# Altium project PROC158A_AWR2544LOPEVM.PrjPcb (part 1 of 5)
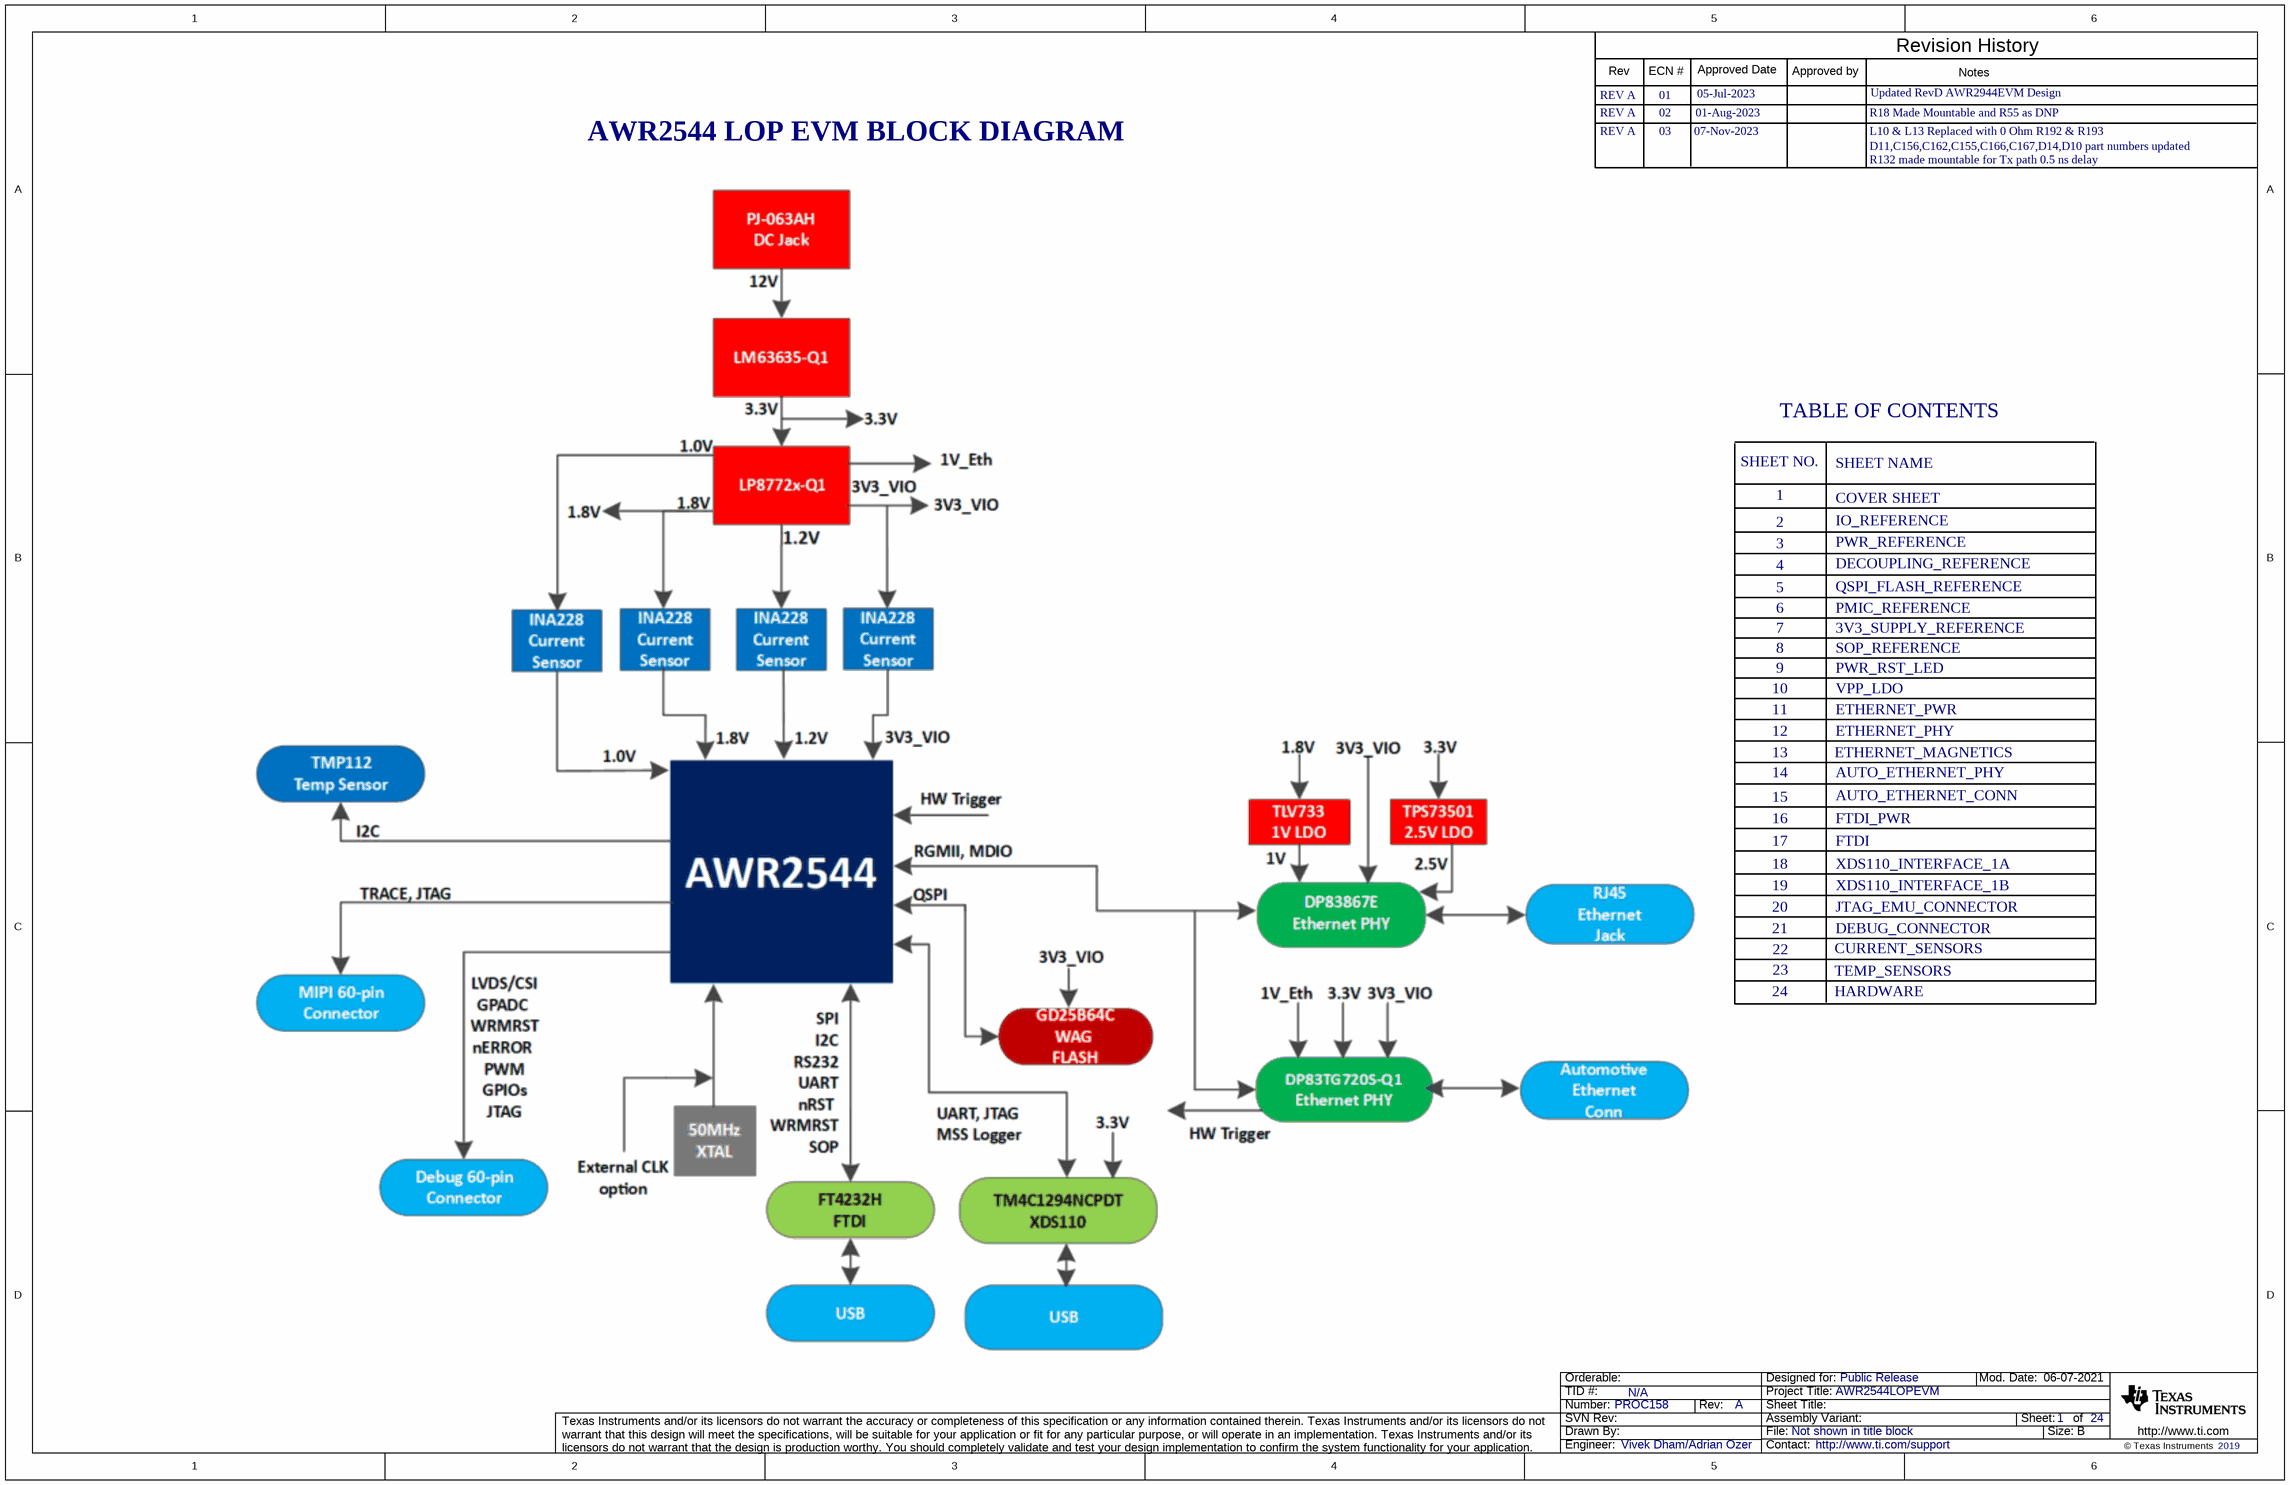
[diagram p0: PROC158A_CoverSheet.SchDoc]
CopyrightYear: 2019; PCB_Layout: Mistral; PCB_Rev: A; PRJ_Customer: Public Release; PRJ_Engineer: Vivek Dham/Adrian Ozer; PRJ_Number: PROC158; PRJ_Title: AWR2544LOPEVM; SCH_Rev: A; TechSupport: http://www.ti.com/support; TID: N/A
24 sheets, 718 parts. Net scope: global (net labels, ports and power ports of the same name join across sheets).
Board file: PROC158A_BRD.PcbDoc
Sheets:
  PROC158A_CoverSheet.SchDoc
  PROC158A_IO_Reference.SchDoc
  PROC158A_PWR_Reference.SchDoc
  PROC158A_Decoupling_Reference.SchDoc
  PROC158A_QSPI_Flash_Reference.SchDoc
  PROC158A_PMIC_Reference.SchDoc
  PROC158A_3V3_Supply_Reference.SchDoc
  PROC158A_SOP_Reference.SchDoc
  PROC158A_PWR_RST_LED.SchDoc
  PROC158A_VPP_LDO.SchDoc
  PROC158A_Ethernet_PWR.SchDoc
  PROC158A_Ethernet_PHY.SchDoc
  PROC158A_Ethernet_Magnetics.SchDoc
  PROC158A_Auto_Ethernet_PHY.SchDoc
  PROC158A_Auto_Ethernet_conn.SchDoc
  PROC158A_FTDI_PWR.SchDoc
  PROC158A_FTDI.SchDoc
  PROC158A_XDS110 Interface_1A.SchDoc
  PROC158A_XDS110 Interface_1B.SchDoc
  PROC158A_JTAG_EMU_Connector.SchDoc
  PROC158A_Debug_Connector.SchDoc
  PROC158A_Current_Sensors.SchDoc
  PROC158A_Temp_Sensor.SchDoc
  PROC158A_Hardware.SchDoc

## Sheet PROC158A_CoverSheet.SchDoc
size 431 x 279 mm; Date: Not shown in title block; ApprovedBy: Not shown in title block; CheckedBy: Not shown in title block; Author: Not shown in title block; CompanyName: Not shown in title block; Engineer: Not shown in title block; Organization: Not shown in title block; Address1: Not shown in title block; Address2: Not shown in title block; Address3: Not shown in title block; Address4: Not shown in title block; DocumentNumber: 1; Revision: Use project parameter SCH_Rev; SheetNumber: 1; SheetTotal: 24; PageSetup: Record=PageOptions¦CenterHorizontal=True¦CenterVertical=True¦PrintScale=1.00¦XCorrection=1.00¦YCorrection=1.00¦PrintKind=0¦BorderSize=5000000¦LeftOffset=0¦BottomOffset=0¦Orientation=2¦PaperLength=1000¦PaperWidth=1000¦Scale=100¦PaperSource=15¦PrintQuality=600¦MediaType=1¦DitherType=10¦PaperKind=Letter¦PrintScaleMode=1

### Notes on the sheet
- REV A
- Rev
- 01
- ECN #
- 05-Jul-2023
- Approved Date
- Approved by
- Updated RevD AWR2944EVM Design
- Revision History
- Notes
- AWR2544 LOP EVM BLOCK DIAGRAM
- 02
- 03
- 07-Nov-2023
- 01-Aug-2023
- R18 Made Mountable and R55 as DNP
- L10 & L13 Replaced with 0 Ohm R192 & R193
- D11,C156,C162,C155,C166,C167,D14,D10 part numbers updated
- R132 made mountable for Tx path 0.5 ns delay
- TABLE OF CONTENTS
- SHEET NO.
- 1
- SHEET NAME
- 2
- 3
- 4
- COVER SHEET
- IO_REFERENCE
- PWR_REFERENCE
- DECOUPLING_REFERENCE
- 5
- 7
- 6
- PMIC_REFERENCE
- QSPI_FLASH_REFERENCE
- 3V3_SUPPLY_REFERENCE
- 10
- 8
- 9
- PWR_RST_LED
- SOP_REFERENCE
- VPP_LDO
- 11
- 12
- 13
- ETHERNET_MAGNETICS
- ETHERNET_PWR
- ETHERNET_PHY
- 15
- 16
- 14
- FTDI_PWR
- AUTO_ETHERNET_CONN
- AUTO_ETHERNET_PHY
- 17
- 18
- 19
- XDS110_INTERFACE_1B
- XDS110_INTERFACE_1A
- FTDI
- 20
- 21
- 22
- CURRENT_SENSORS
- JTAG_EMU_CONNECTOR
- DEBUG_CONNECTOR
- 24
- 23
- HARDWARE
- TEMP_SENSORS

## Sheet PROC158A_IO_Reference.SchDoc
size A2; Date: Not shown in title block; ApprovedBy: Not shown in title block; CheckedBy: Not shown in title block; Author: Not shown in title block; CompanyName: Not shown in title block; Engineer: Not shown in title block; Organization: Not shown in title block; Address1: Not shown in title block; Address2: Not shown in title block; Address3: Not shown in title block; Address4: Not shown in title block; DocumentNumber: 2; Revision: Use project parameter SCH_Rev; SheetNumber: 2; SheetTotal: 24; PageSetup: Record=PageOptions¦CenterHorizontal=True¦CenterVertical=True¦PrintScale=1.00¦XCorrection=1.00¦YCorrection=1.00¦PrintKind=0¦BorderSize=5000000¦LeftOffset=0¦BottomOffset=0¦Orientation=2¦PaperLength=1000¦PaperWidth=1000¦Scale=100¦PaperSource=15¦PrintQuality=600¦MediaType=1¦DitherType=10¦PaperKind=Letter¦PrintScaleMode=1
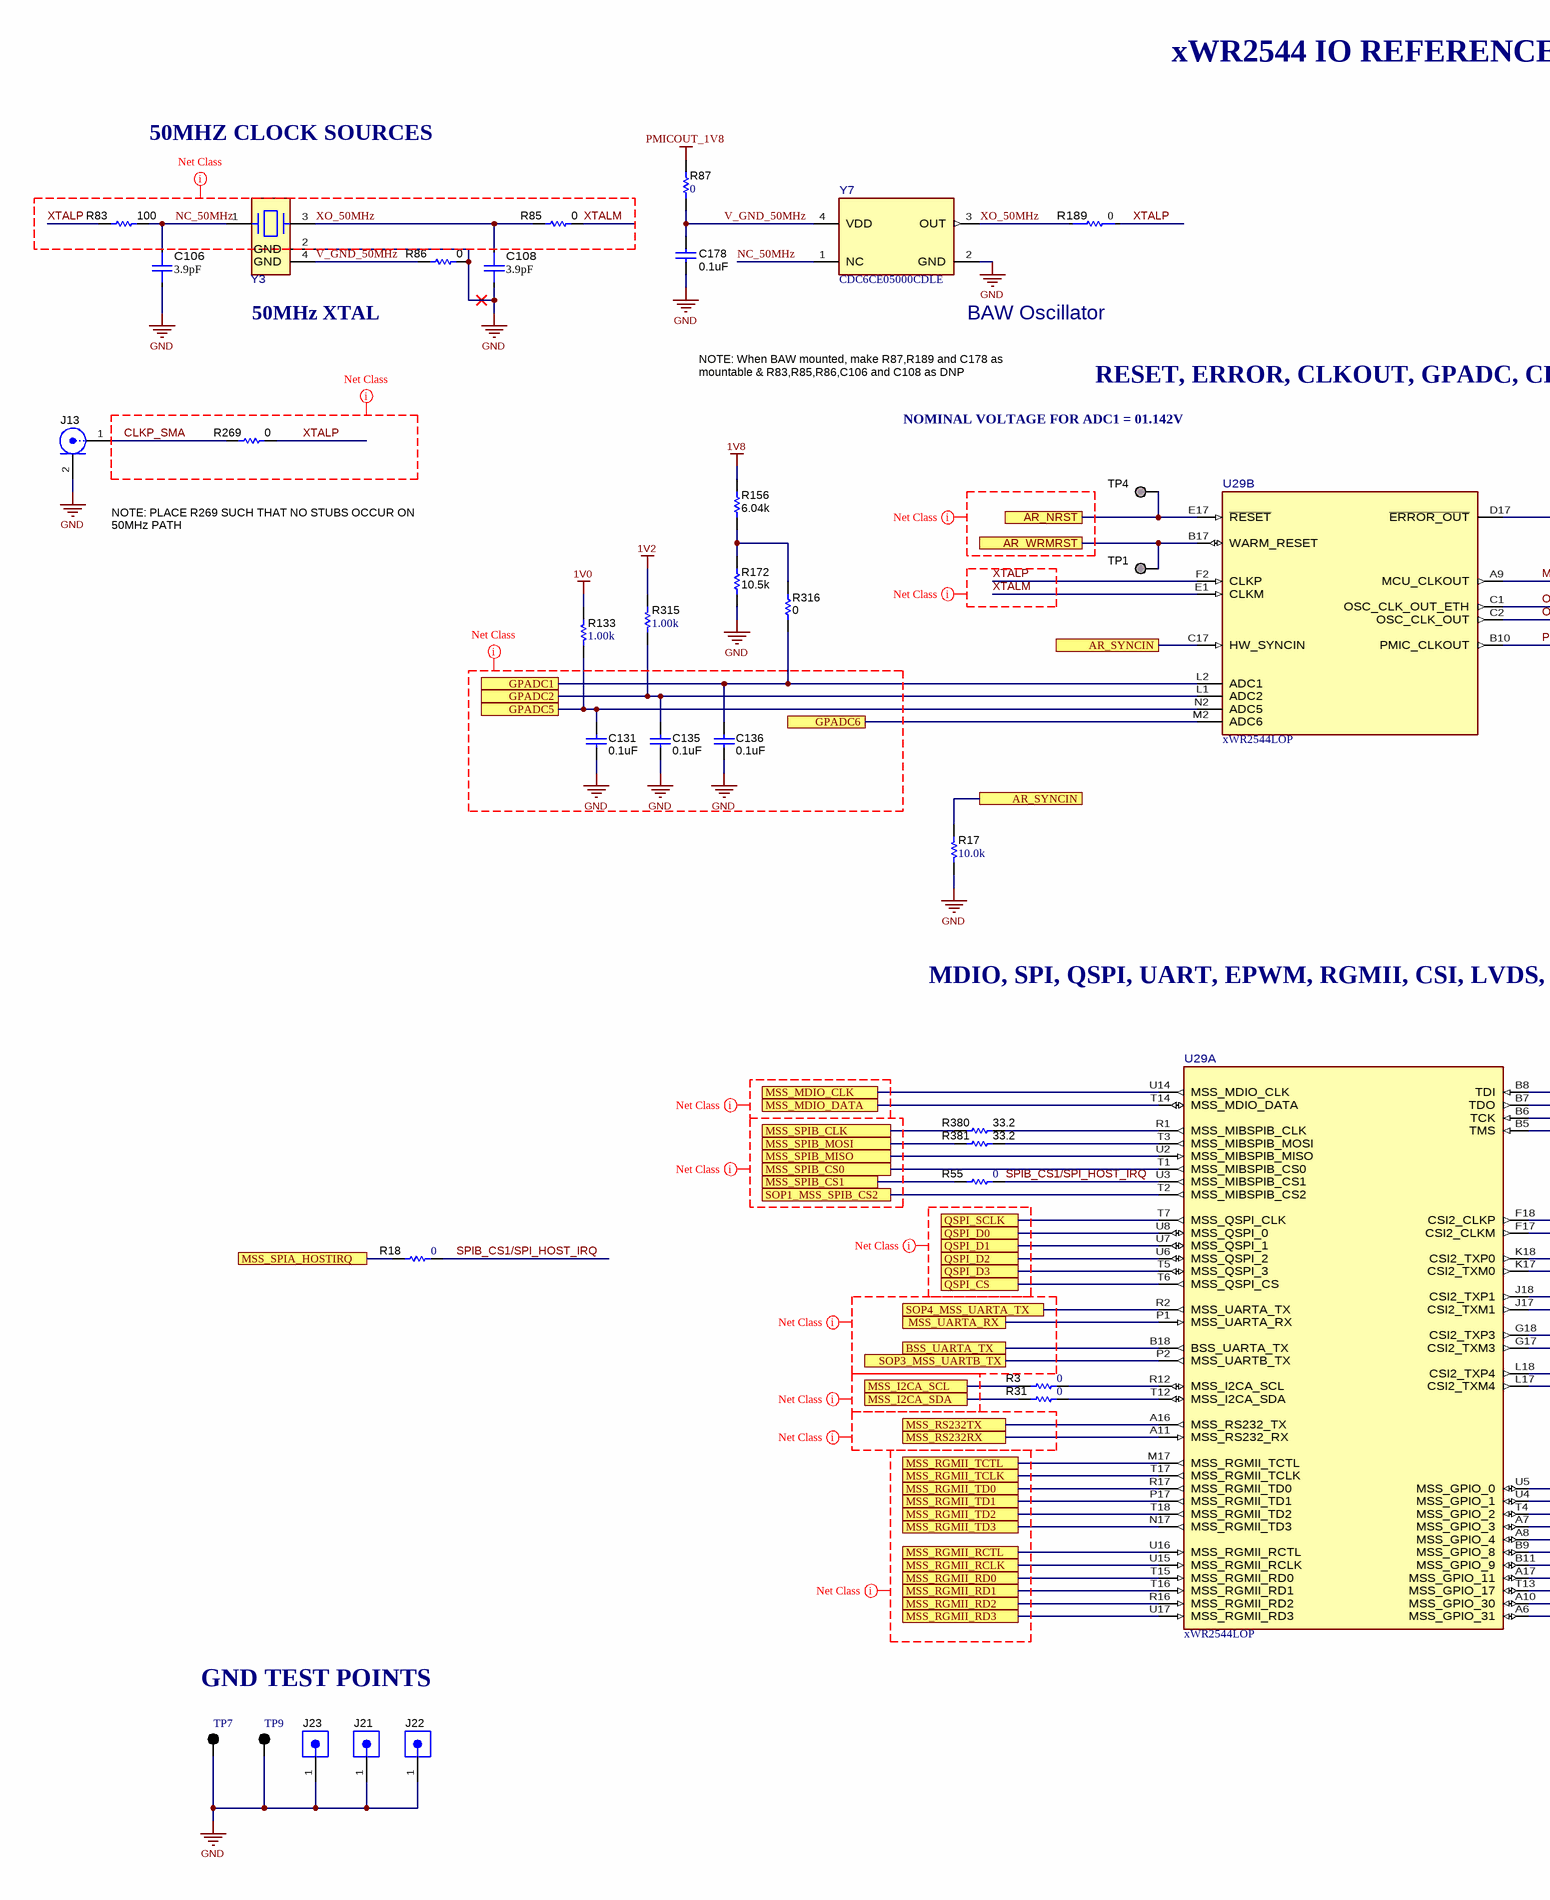
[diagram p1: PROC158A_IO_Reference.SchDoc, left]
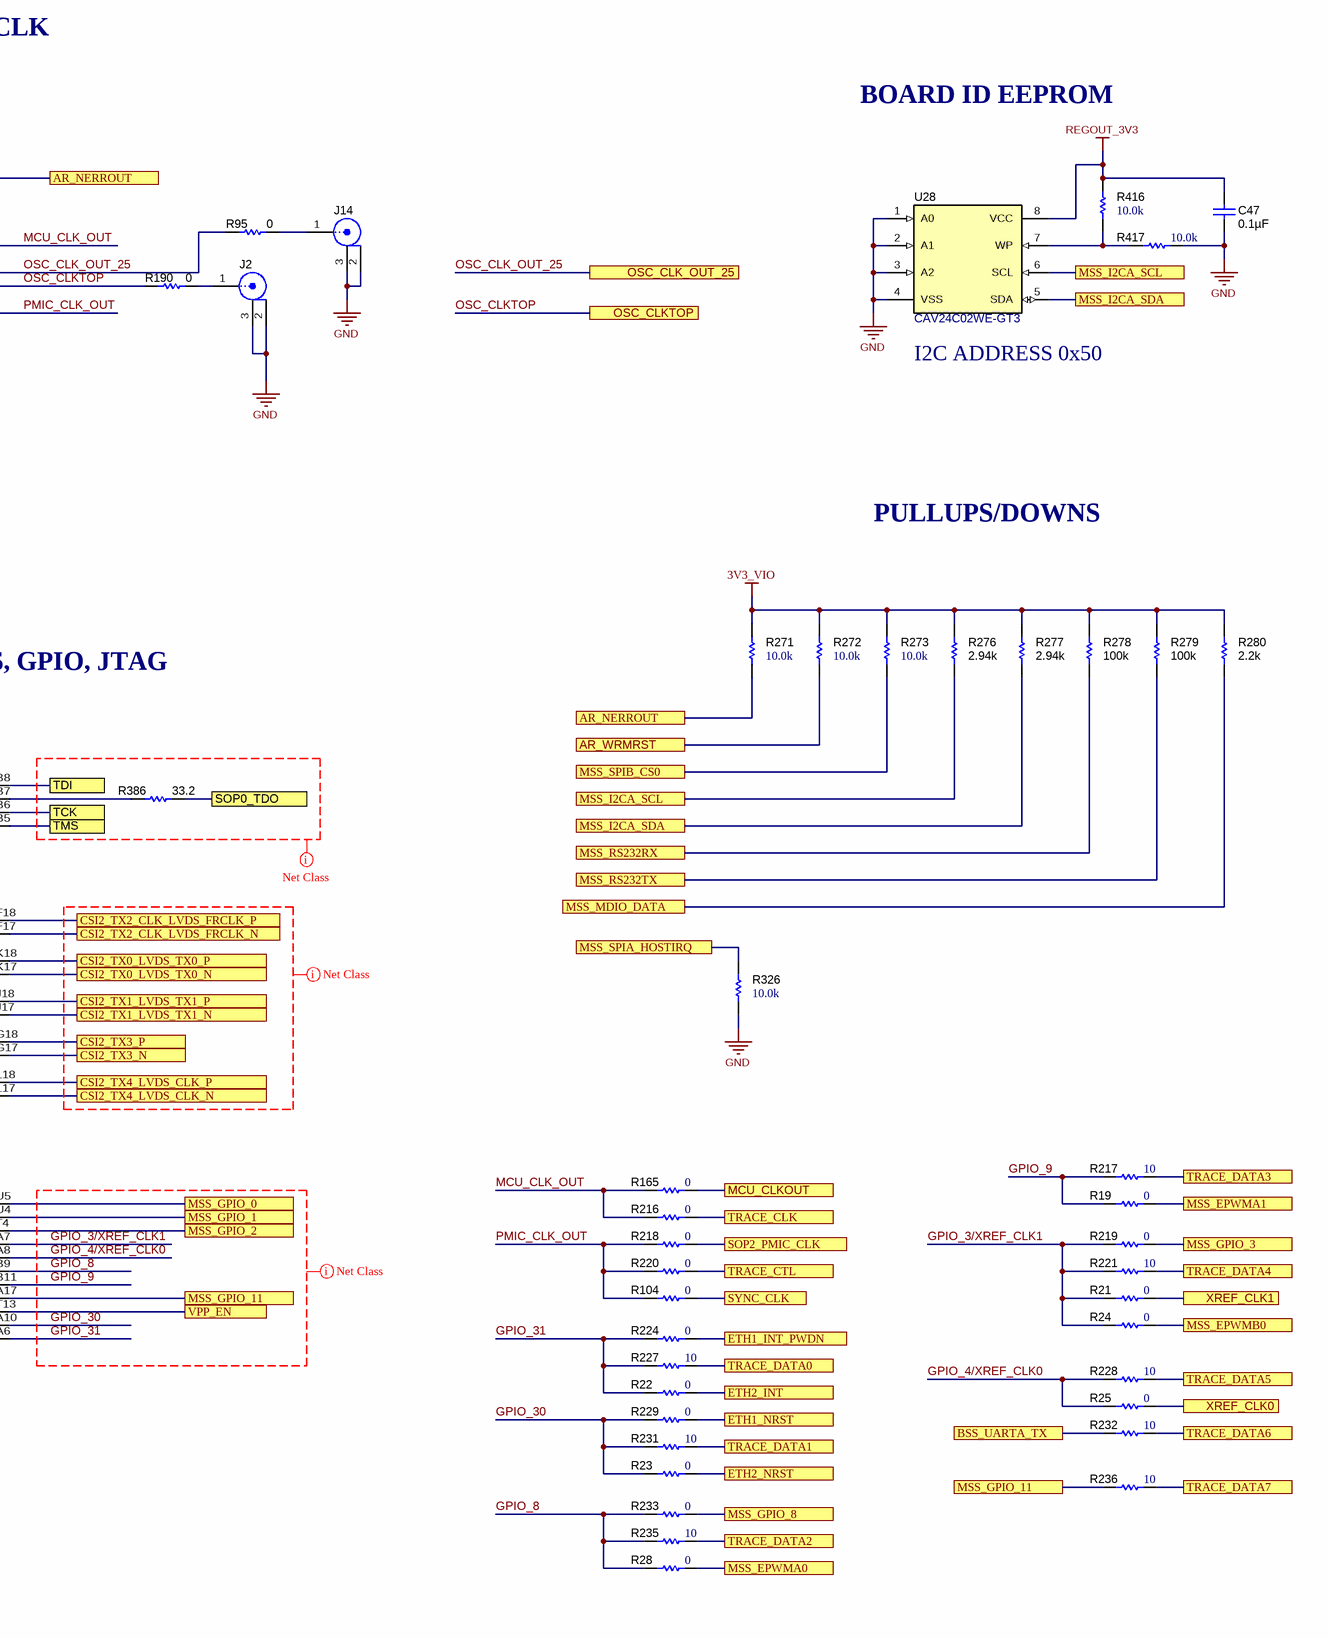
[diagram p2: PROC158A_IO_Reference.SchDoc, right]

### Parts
C47  ValueDisplayed: 0.1µF  [0402L]  (hidden comment: C0402C104K8RACTU)
C106  ValueDisplayed: 3.9pF  [FP-GCM1555C1H3R9BA16D_0402-MFG]  (hidden comment: GCM1555C1H3R9BA16D)
C108  ValueDisplayed: 3.9pF  [FP-GCM1555C1H3R9BA16D_0402-MFG]  (hidden comment: GCM1555C1H3R9BA16D)
C131  ValueDisplayed: 0.1uF  [0402L]  (hidden comment: GCM155R71C104KA55D)
C135  ValueDisplayed: 0.1uF  [0402L]  (hidden comment: GCM155R71C104KA55D)
C136  ValueDisplayed: 0.1uF  [0402L]  (hidden comment: GCM155R71C104KA55D)
C178  ValueDisplayed: 0.1uF  [0402L]  (hidden comment: GCM155R71C104KA55D)
J2  128-0711-201  [Johnson_128-0711-201]  (value not drawn)
J13  142-0711-201  [142-0711-201]  (value not drawn)
J14  128-0711-201  [Johnson_128-0711-201]  (value not drawn)
J21  GBC01SFBN-M30  [Sullins_GBC01SFBN-M30]  (value not drawn)
J22  GBC01SFBN-M30  [Sullins_GBC01SFBN-M30]  (value not drawn)
J23  GBC01SFBN-M30  [Sullins_GBC01SFBN-M30]  (value not drawn)
R3  ValueDisplayed: 0  [0402L]  (hidden comment: ERJ-2GE0R00X)
R17  ValueDisplayed: 10.0k  [0402L]  (hidden comment: CRCW040210K0FKED)
R18  ValueDisplayed: 0  [0201L]  (hidden comment: CRCW02010000Z0ED)
R19  value 0  [0402L]  (hidden comment: ERJ-2GE0R00X)
R21  ValueDisplayed: 0  [0201L]  (hidden comment: CRCW02010000Z0ED)
R22  ValueDisplayed: 0  [0402L]  (hidden comment: ERJ-2GE0R00X)
R23  ValueDisplayed: 0  [0402L]  (hidden comment: ERJ-2GE0R00X)
R24  ValueDisplayed: 0  [0201L]  (hidden comment: CRCW02010000Z0ED)
R25  ValueDisplayed: 0  [0201L]  (hidden comment: CRCW02010000Z0ED)
R28  value 0  [0402L]  (hidden comment: ERJ-2GE0R00X)
R31  ValueDisplayed: 0  [0402L]  (hidden comment: ERJ-2GE0R00X)
R55  ValueDisplayed: 0  [0402L]  (hidden comment: ERJ-2GE0R00X)
R83  ValueDisplayed: 100  [0402L]  (hidden comment: ERJ-2GEJ101X)
R85  ValueDisplayed: 0  [0402L]  (hidden comment: ERJ-2GE0R00X)
R86  ValueDisplayed: 0  [0402L]  (hidden comment: ERJ-2GE0R00X)
R87  ValueDisplayed: 0  [0402L]  (hidden comment: ERJ-2GE0R00X)
R95  ValueDisplayed: 0  [0402L]  (hidden comment: ERJ-2GE0R00X)
R104  ValueDisplayed: 0  [0201L]  (hidden comment: CRCW02010000Z0ED)
R133  ValueDisplayed: 1.00k  [0402L]  (hidden comment: CRCW04021K00FKED)
R156  ValueDisplayed: 6.04k  [0402L]  (hidden comment: CRCW04026K04FKED)
R165  ValueDisplayed: 0  [0201L]  (hidden comment: CRCW02010000Z0ED)
R172  ValueDisplayed: 10.5k  [0402L]  (hidden comment: CRCW040210K5FKED)
R189  Res_ohm: 0  [FP-HCJ0603ZT0R00_0603-MFG]  (hidden comment: HCJ0603ZT0R00)
R190  ValueDisplayed: 0  [0402L]  (hidden comment: ERJ-2GE0R00X)
R216  ValueDisplayed: 0  [0201L]  (hidden comment: CRCW02010000Z0ED)
R217  ValueDisplayed: 10  [0201L]  (hidden comment: RC0201JR-0710RL)
R218  ValueDisplayed: 0  [0201L]  (hidden comment: CRCW02010000Z0ED)
R219  ValueDisplayed: 0  [0201L]  (hidden comment: CRCW02010000Z0ED)
R220  ValueDisplayed: 0  [0201L]  (hidden comment: CRCW02010000Z0ED)
R221  ValueDisplayed: 10  [0201L]  (hidden comment: RC0201JR-0710RL)
R224  ValueDisplayed: 0  [0201L]  (hidden comment: CRCW02010000Z0ED)
R227  ValueDisplayed: 10  [0201L]  (hidden comment: RC0201JR-0710RL)
R228  ValueDisplayed: 10  [0201L]  (hidden comment: RC0201JR-0710RL)
R229  ValueDisplayed: 0  [0201L]  (hidden comment: CRCW02010000Z0ED)
R231  ValueDisplayed: 10  [0201L]  (hidden comment: RC0201JR-0710RL)
R232  ValueDisplayed: 10  [0201L]  (hidden comment: RC0201JR-0710RL)
R233  value 0  [0402L]  (hidden comment: ERJ-2GE0R00X)
R235  ValueDisplayed: 10  [0201L]  (hidden comment: RC0201JR-0710RL)
R236  ValueDisplayed: 10  [0201L]  (hidden comment: RC0201JR-0710RL)
R269  ValueDisplayed: 0  [0402L]  (hidden comment: ERJ-2GE0R00X)
R271  ValueDisplayed: 10.0k  [0402L]  (hidden comment: CRCW040210K0FKED)
R272  ValueDisplayed: 10.0k  [0402L]  (hidden comment: CRCW040210K0FKED)
R273  ValueDisplayed: 10.0k  [0402L]  (hidden comment: CRCW040210K0FKED)
R276  ValueDisplayed: 2.94k  [0402L]  (hidden comment: CRCW04022K94FKED)
R277  ValueDisplayed: 2.94k  [0402L]  (hidden comment: CRCW04022K94FKED)
R278  ValueDisplayed: 100k  [0402L]  (hidden comment: CRCW0402100KFKED)
R279  ValueDisplayed: 100k  [0402L]  (hidden comment: CRCW0402100KFKED)
R280  ValueDisplayed: 2.2k  [0402L]  (hidden comment: CRCW04022K20JNED)
R315  ValueDisplayed: 1.00k  [0402L]  (hidden comment: CRCW04021K00FKED)
R316  ValueDisplayed: 0  [0402L]  (hidden comment: ERJ-2GE0R00X)
R326  ValueDisplayed: 10.0k  [0402L]  (hidden comment: CRCW040210K0FKED)
R380  ValueDisplayed: 33.2  [0402L]  (hidden comment: CRCW040233R2FKED)
R381  ValueDisplayed: 33.2  [0402L]  (hidden comment: CRCW040233R2FKED)
R386  ValueDisplayed: 33.2  [0402L]  (hidden comment: CRCW040233R2FKED)
R416  ValueDisplayed: 10.0k  [0402L]  (hidden comment: CRCW040210K0FKED)
R417  ValueDisplayed: 10.0k  [0402L]  (hidden comment: CRCW040210K0FKED)
TP1  TESTPOINT  [TP_25MIL-SMT]  (value not drawn)  (no BOM)
TP4  TESTPOINT  [TP_25MIL-SMT]  (value not drawn)  (no BOM)
TP7  5001  [Keystone5001]  (value not drawn)
TP9  5001  [Keystone5001]  (value not drawn)
U28  CAV24C02WE-GT3  [SOIC-8]
U29  xWR2544LOP  [0-IPC_C]  (parts A,B of 6)
Y3  NX2016SA-50M-STD-CZS-3  [FP-NX2016SA-50M-STD-CZS-3_SMT4_2MM0_1MM6-MFG]  (value not drawn)
Y7  CDC6CE05000CDLE  [DLE0004A-MFG]

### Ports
AR_NERROUT, AR_NRST, AR_SYNCIN, AR_WRMRST, BSS_UARTA_TX, CSI2_TX0_LVDS_TX0_N, CSI2_TX0_LVDS_TX0_P, CSI2_TX1_LVDS_TX1_N, CSI2_TX1_LVDS_TX1_P, CSI2_TX2_CLK_LVDS_FRCLK_N, CSI2_TX2_CLK_LVDS_FRCLK_P, CSI2_TX3_N, CSI2_TX3_P, CSI2_TX4_LVDS_CLK_N, CSI2_TX4_LVDS_CLK_P, ETH1_INT_PWDN, ETH1_NRST, ETH2_INT, ETH2_NRST, GPADC1, GPADC2, GPADC5, GPADC6, MCU_CLKOUT, MSS_EPWMA0, MSS_EPWMA1, MSS_EPWMB0, MSS_GPIO_0, MSS_GPIO_1, MSS_GPIO_2, MSS_GPIO_3, MSS_GPIO_8, MSS_GPIO_11, MSS_I2CA_SCL, MSS_I2CA_SDA, MSS_MDIO_CLK, MSS_MDIO_DATA, MSS_RGMII_RCLK, MSS_RGMII_RCTL, MSS_RGMII_RD0, MSS_RGMII_RD1, MSS_RGMII_RD2, MSS_RGMII_RD3, MSS_RGMII_TCLK, MSS_RGMII_TCTL, MSS_RGMII_TD0, MSS_RGMII_TD1, MSS_RGMII_TD2, MSS_RGMII_TD3, MSS_RS232RX, MSS_RS232TX, MSS_SPIA_HOSTIRQ, MSS_SPIB_CLK, MSS_SPIB_CS0, MSS_SPIB_CS1, MSS_SPIB_MISO, MSS_SPIB_MOSI, MSS_UARTA_RX, OSC_CLK_OUT_25, OSC_CLKTOP, QSPI_CS, QSPI_D0, QSPI_D1, QSPI_D2, QSPI_D3, QSPI_SCLK, SOP0_TDO, SOP1_MSS_SPIB_CS2, SOP2_PMIC_CLK, SOP3_MSS_UARTB_TX, SOP4_MSS_UARTA_TX, SYNC_CLK, TCK, TDI, TMS, TRACE_CLK, TRACE_CTL, TRACE_DATA0, TRACE_DATA1, TRACE_DATA2, TRACE_DATA3, TRACE_DATA4, TRACE_DATA5, TRACE_DATA6, TRACE_DATA7, VPP_EN, XREF_CLK0, XREF_CLK1

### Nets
1V0: R133.2
1V2: R315.2
1V8: R156.2
3V3_VIO: R271.2 R272.2 R273.2 R276.2 R277.2 R278.2 R279.2 R280.2
GND: C47.1 C106.2 C108.2 C131.1 C135.1 C136.1 C178.1 J2.2 J2.3 J13.2 J14.2 J14.3 J21.1 J22.1 J23.1 R17.1 R86.1 R172.1 R326.1 R417.1 TP7.1 TP9.1 U28.1(A0) U28.2(A1) U28.3(A2) U28.4(VSS) Y3.2(GND) Y7.2(GND)
PMICOUT_1V8: R87.1
REGOUT_3V3: C47.2 R416.2 U28.8(VCC)
AR_NERROUT: R271.1 U29.D17(~{ERROR_OUT}) ; port AR_NERROUT
AR_NRST: TP4.1 U29.E17(~{RESET}) ; port AR_NRST
AR_SYNCIN: R17.2 U29.C17(HW_SYNCIN) ; port AR_SYNCIN
AR_WRMRST: R272.1 TP1.1 U29.B17(WARM_RESET) ; port AR_WRMRST
BSS_UARTA_TX: R232.2 U29.B18(BSS_UARTA_TX) ; port BSS_UARTA_TX
CLKP_SMA: J13.1 R269.2
CSI2_TX0_LVDS_TX0_N: U29.K17(CSI2_TXM0) ; port CSI2_TX0_LVDS_TX0_N
CSI2_TX0_LVDS_TX0_P: U29.K18(CSI2_TXP0) ; port CSI2_TX0_LVDS_TX0_P
CSI2_TX1_LVDS_TX1_N: U29.J17(CSI2_TXM1) ; port CSI2_TX1_LVDS_TX1_N
CSI2_TX1_LVDS_TX1_P: U29.J18(CSI2_TXP1) ; port CSI2_TX1_LVDS_TX1_P
CSI2_TX2_CLK_LVDS_FRCLK_N: U29.F17(CSI2_CLKM) ; port CSI2_TX2_CLK_LVDS_FRCLK_N
CSI2_TX2_CLK_LVDS_FRCLK_P: U29.F18(CSI2_CLKP) ; port CSI2_TX2_CLK_LVDS_FRCLK_P
CSI2_TX3_N: U29.G17(CSI2_TXM3) ; port CSI2_TX3_N
CSI2_TX3_P: U29.G18(CSI2_TXP3) ; port CSI2_TX3_P
CSI2_TX4_LVDS_CLK_N: U29.L17(CSI2_TXM4) ; port CSI2_TX4_LVDS_CLK_N
CSI2_TX4_LVDS_CLK_P: U29.L18(CSI2_TXP4) ; port CSI2_TX4_LVDS_CLK_P
ETH1_INT_PWDN: R224.2 ; port ETH1_INT_PWDN
ETH1_NRST: R229.2 ; port ETH1_NRST
ETH2_INT: R22.1 ; port ETH2_INT
ETH2_NRST: R23.1 ; port ETH2_NRST
GPADC1: C136.2 R316.1 U29.L2(ADC1) ; port GPADC1
GPADC2: C135.2 R315.1 U29.L1(ADC2) ; port GPADC2
GPADC5: C131.2 R133.1 U29.N2(ADC5) ; port GPADC5
GPADC6: U29.M2(ADC6) ; port GPADC6
GPIO_3/XREF_CLK1: R21.1 R24.1 R219.1 R221.2 U29.A7(MSS_GPIO_3)
GPIO_4/XREF_CLK0: R25.1 R228.2 U29.A8(MSS_GPIO_4)
GPIO_8: R28.1 R233.1 R235.2 U29.B9(MSS_GPIO_8)
GPIO_9: R19.1 R217.2 U29.B11(MSS_GPIO_9)
GPIO_30: R23.2 R229.1 R231.2 U29.A10(MSS_GPIO_30)
GPIO_31: R22.2 R224.1 R227.2 U29.A6(MSS_GPIO_31)
MCU_CLK_OUT: R165.1 R216.1 U29.A9(MCU_CLKOUT)
MCU_CLKOUT: R165.2 ; port MCU_CLKOUT
MSS_EPWMA0: R28.2 ; port MSS_EPWMA0
MSS_EPWMA1: R19.2 ; port MSS_EPWMA1
MSS_EPWMB0: R24.2 ; port MSS_EPWMB0
MSS_GPIO_0: U29.U5(MSS_GPIO_0) ; port MSS_GPIO_0
MSS_GPIO_1: U29.U4(MSS_GPIO_1) ; port MSS_GPIO_1
MSS_GPIO_2: U29.T4(MSS_GPIO_2) ; port MSS_GPIO_2
MSS_GPIO_3: R219.2 ; port MSS_GPIO_3
MSS_GPIO_8: R233.2 ; port MSS_GPIO_8
MSS_GPIO_11: R236.2 U29.A17(MSS_GPIO_11) ; port MSS_GPIO_11
MSS_I2CA_SCL: R3.1 R276.1 U28.6(SCL) ; port MSS_I2CA_SCL
MSS_I2CA_SDA: R31.1 R277.1 U28.5(SDA) ; port MSS_I2CA_SDA
MSS_MDIO_CLK: U29.U14(MSS_MDIO_CLK) ; port MSS_MDIO_CLK
MSS_MDIO_DATA: R280.1 U29.T14(MSS_MDIO_DATA) ; port MSS_MDIO_DATA
MSS_RGMII_RCLK: U29.U15(MSS_RGMII_RCLK) ; port MSS_RGMII_RCLK
MSS_RGMII_RCTL: U29.U16(MSS_RGMII_RCTL) ; port MSS_RGMII_RCTL
MSS_RGMII_RD0: U29.T15(MSS_RGMII_RD0) ; port MSS_RGMII_RD0
MSS_RGMII_RD1: U29.T16(MSS_RGMII_RD1) ; port MSS_RGMII_RD1
MSS_RGMII_RD2: U29.R16(MSS_RGMII_RD2) ; port MSS_RGMII_RD2
MSS_RGMII_RD3: U29.U17(MSS_RGMII_RD3) ; port MSS_RGMII_RD3
MSS_RGMII_TCLK: U29.T17(MSS_RGMII_TCLK) ; port MSS_RGMII_TCLK
MSS_RGMII_TCTL: U29.M17(MSS_RGMII_TCTL) ; port MSS_RGMII_TCTL
MSS_RGMII_TD0: U29.R17(MSS_RGMII_TD0) ; port MSS_RGMII_TD0
MSS_RGMII_TD1: U29.P17(MSS_RGMII_TD1) ; port MSS_RGMII_TD1
MSS_RGMII_TD2: U29.T18(MSS_RGMII_TD2) ; port MSS_RGMII_TD2
MSS_RGMII_TD3: U29.N17(MSS_RGMII_TD3) ; port MSS_RGMII_TD3
MSS_RS232RX: R278.1 U29.A11(MSS_RS232_RX) ; port MSS_RS232RX
MSS_RS232TX: R279.1 U29.A16(MSS_RS232_TX) ; port MSS_RS232TX
MSS_SPIA_HOSTIRQ: R18.1 R326.2 ; port MSS_SPIA_HOSTIRQ
MSS_SPIB_CLK: R380.1 ; port MSS_SPIB_CLK
MSS_SPIB_CS0: R273.1 U29.T1(MSS_MIBSPIB_CS0) ; port MSS_SPIB_CS0
MSS_SPIB_CS1: R55.1 ; port MSS_SPIB_CS1
MSS_SPIB_MISO: U29.U2(MSS_MIBSPIB_MISO) ; port MSS_SPIB_MISO
MSS_SPIB_MOSI: R381.1 ; port MSS_SPIB_MOSI
MSS_UARTA_RX: U29.P1(MSS_UARTA_RX) ; port MSS_UARTA_RX
NC_50MHz: C106.1 R83.2 Y3.1(1_XTAL) Y7.1(NC)
OSC_CLK_OUT_25: R95.2 U29.C1(OSC_CLK_OUT_ETH) ; port OSC_CLK_OUT_25
OSC_CLKTOP: R190.2 U29.C2(OSC_CLK_OUT) ; port OSC_CLKTOP
PMIC_CLK_OUT: R104.1 R218.1 R220.1 U29.B10(PMIC_CLKOUT)
QSPI_CS: U29.T6(MSS_QSPI_CS) ; port QSPI_CS
QSPI_D0: U29.U8(MSS_QSPI_0) ; port QSPI_D0
QSPI_D1: U29.U7(MSS_QSPI_1) ; port QSPI_D1
QSPI_D2: U29.U6(MSS_QSPI_2) ; port QSPI_D2
QSPI_D3: U29.T5(MSS_QSPI_3) ; port QSPI_D3
QSPI_SCLK: U29.T7(MSS_QSPI_CLK) ; port QSPI_SCLK
SOP0_TDO: R386.1 ; port SOP0_TDO
SOP1_MSS_SPIB_CS2: U29.T2(MSS_MIBSPIB_CS2) ; port SOP1_MSS_SPIB_CS2
SOP2_PMIC_CLK: R218.2 ; port SOP2_PMIC_CLK
SOP3_MSS_UARTB_TX: U29.P2(MSS_UARTB_TX) ; port SOP3_MSS_UARTB_TX
SOP4_MSS_UARTA_TX: U29.R2(MSS_UARTA_TX) ; port SOP4_MSS_UARTA_TX
SPIB_CS1/SPI_HOST_IRQ: R18.2 R55.2 U29.U3(MSS_MIBSPIB_CS1)
SYNC_CLK: R104.2 ; port SYNC_CLK
TCK: U29.B6(TCK) ; port TCK
TDI: U29.B8(TDI) ; port TDI
TMS: U29.B5(TMS) ; port TMS
TRACE_CLK: R216.2 ; port TRACE_CLK
TRACE_CTL: R220.2 ; port TRACE_CTL
TRACE_DATA0: R227.1 ; port TRACE_DATA0
TRACE_DATA1: R231.1 ; port TRACE_DATA1
TRACE_DATA2: R235.1 ; port TRACE_DATA2
TRACE_DATA3: R217.1 ; port TRACE_DATA3
TRACE_DATA4: R221.1 ; port TRACE_DATA4
TRACE_DATA5: R228.1 ; port TRACE_DATA5
TRACE_DATA6: R232.1 ; port TRACE_DATA6
TRACE_DATA7: R236.1 ; port TRACE_DATA7
V_GND_50MHz: C178.2 R86.2 R87.2 Y3.4(GND) Y7.4(VDD)
VPP_EN: U29.T13(MSS_GPIO_17) ; port VPP_EN
XO_50MHz: C108.1 R85.2 R189.1 Y3.3(2_XTAL) Y7.3(OUT)
XREF_CLK0: R25.2 ; port XREF_CLK0
XREF_CLK1: R21.2 ; port XREF_CLK1
XTALM: R85.1 U29.E1(CLKM)
XTALP: R83.1 R189.2 R269.1 U29.F2(CLKP)
NetJ2_1: J2.1 R190.1
NetJ14_1: J14.1 R95.1
NetR3_2: R3.2 U29.R12(MSS_I2CA_SCL)
NetR31_2: R31.2 U29.T12(MSS_I2CA_SDA)
NetR156_1: R156.1 R172.2 R316.2
NetR380_2: R380.2 U29.R1(MSS_MIBSPIB_CLK)
NetR381_2: R381.2 U29.T3(MSS_MIBSPIB_MOSI)
NetR386_2: R386.2 U29.B7(TDO)
NetR416_1: R416.1 R417.2 U28.7(WP)

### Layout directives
net class 40MHz_CLK: CLKP_SMA, NC_50MHz, XO_50MHz, XTALM, XTALP
net class GPADC: GND
net class I2C: (no net found under the mark)
net class MSS_SPIB: (no net found under the mark)
net class QSPI: (no net found under the mark)
net class CSI: (no net found under the mark)
net class JTAG: (no net found under the mark)
net class GPIO: GPIO_3/XREF_CLK1, GPIO_4/XREF_CLK0, GPIO_8, GPIO_9, GPIO_30, GPIO_31
net class RESET: (no net found under the mark)
net class MDIO: (no net found under the mark)
net class UART: (no net found under the mark)
net class RGMII_TX_RX: (no net found under the mark)

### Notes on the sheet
- xWR2544 IO REFERENCE
- 50MHZ CLOCK SOURCES
- (near Y3) 50MHz XTAL
- (near Y7) BAW Oscillator
- NOTE: When BAW mounted, make R87,R189 and C178 as mountable & R83,R85,R86,C106 and C108 as DNP
- RESET, ERROR, CLKOUT, GPADC, CLK
- NOMINAL VOLTAGE FOR ADC1 = 01.142V
- BOARD ID EEPROM
- NOTE: PLACE R269 SUCH THAT NO STUBS OCCUR ON 50MHz PATH
- (near U28) I2C ADDRESS 0x50
- PULLUPS/DOWNS
- MDIO, SPI, QSPI, UART, EPWM, RGMII, CSI, LVDS, GPIO, JTAG
- GND TEST POINTS

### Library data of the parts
C47 = CMP-0078241-1: CAP, CERM, 0.1 µF, 10 V,+/- 10%, X7R, 0402; Manufacturer: Kemet; TaMin_C: -55°C; Polarized: N; SizeAreaWB_mm2: 3; U/M: EA; Value: 0.1uF; TaMax_C: 125°C; SizeZ_mm: 0.6; SizeX_mm: 1; SizeY_mm: 0.5; Cap_Case: 0402; Value2: 10V; Cap_F: 100nF; AEC Category: Q200
C106 C108 = CMP-0048219-1: Ceramic Capacitor for Automotive 3.9pF ±0.1pF 50VDC C0G 0402 Paper T/R; Manufacturer: Murata; AEC Grade: Grade 1; AEC Qualified: Yes; SizeZ_mm: 0.55mm; TempCo: 30ppm/°C; VDC_V: 50V
C131 C135 C136 C178 = CMP-0006351-2: CAP, CERM, 0.1 uF, 16 V, +/- 10%, X7R, 0402; Manufacturer: MuRata; TaMin_C: -55°C; Polarized: N; SizeAreaWB_mm2: 3; Value1: Unknown; U/M: EA; Value: 0.1uF; TaMax_C: 125°C; SizeZ_mm: 0.6; SizeX_mm: 1; SizeY_mm: 0.5; Cap_Case: 0402; Value2: 16V; CompType: Capacitor; Cap_F: 100nF; AEC Category: Q200
J2 J14 = CMP-0055788-1: UMC Straight Jack Receptacle, 50 Ohm, Gold, SMT; Manufacturer: Cinch Connectivity; CNHeader: FALSE; Gender: Female
J13 = CMP-0055823-2: Connector, SMA Jack, Vertical, Gold, SMD; Manufacturer: Cinch Connectivity; Green_REACh: Incomplete; Green_Lifecycle: Not Set; Gender: Female
J21-J23 = CMP-0084373-1: Header, 1x1, Gold, SMT; Manufacturer: Sullins Connector Solutions; Cert_UL: Y; Current_A: 3A; Gender: Male; Row_Count: 1; Shrouded: N
R3 R22 R23 R31 R55 R85-R87 R95 R190 R269 R316 = CMP-0026992-3: RES, 0, 5%, 0.1 W, AEC-Q200 Grade 0, 0402; Manufacturer: Panasonic; Power_W: 100mW; TempCo: 600 ppm/C; Value_Code: 0000; Value: 0; EIA_Code: E24; SizeX_mm: 1; SizeY_mm: 0.5; SizeZ_mm: 0.6; Value2: 0.1W; AEC Qualified: Y; VDC_V: 50V; AEC Category: Q200; SizeAreaWB_mm2: 3
R17 R271-R273 R326 R416 R417 = CMP-0025958-3: RES, 10.0 k, 1%, 0.063 W, AEC-Q200 Grade 0, 0402; Manufacturer: Vishay-Dale; Power_W: 63mW; TempCo: 100 ppm/C; Value_Code: 10k0; Value: 10.0k; EIA_Code: E96; Res_ohm: 10k; SizeX_mm: 1; SizeY_mm: 0.5; SizeZ_mm: 0.6; Value2: 0.063W; CompType: Resistor; AEC Qualified: Y; VDC_V: 50V; AEC Category: Q200; AEC Grade: 0; INSTALLATION: DNP
R18 R21 R24 R25 R104 R165 R216 R218-R220 R224 R229 = CMP-0027008-4: RES, 0, 5%, 0.05 W, 0201; Manufacturer: Vishay-Dale; Power_W: 50mW; TempCo: ppm/C; Value_Code: 0000; Value: 0; EIA_Code: E24; SizeX_mm: 0.6; SizeY_mm: 0.3; SizeZ_mm: 0.26; Value2: 0.05W; SizeArea_mm2: 0.18; AEC Qualified: N; AEC Category: Q200
R19 R28 R233 = CMP-0026992-3: RES, 0, 5%, 0.1 W, AEC-Q200 Grade 0, 0402; Manufacturer: Panasonic; Power_W: 100mW; TempCo: 600 ppm/C; Value_Code: 0000; EIA_Code: E24; SizeX_mm: 1; SizeY_mm: 0.5; SizeZ_mm: 0.6; Value2: 0.1W; AEC Qualified: Y; VDC_V: 50V; AEC Category: Q200; SizeAreaWB_mm2: 3
R83 = CMP-0026993-2: RES, 100, 5%, 0.1 W, AEC-Q200 Grade 0, 0402; Manufacturer: Panasonic; Power_W: 100mW; TempCo: 200 ppm/C; Value_Code: 100R; U/M: EA; Value: 100; EIA_Code: E24; SizeX_mm: 1; SizeY_mm: 0.5; SizeZ_mm: 0.6; Value2: 0.1W; AEC Qualified: Y; AEC Grade: 0; AEC Category: Q200
R133 R315 = CMP-0026071-3: RES, 1.00 k, 1%, 0.063 W, AEC-Q200 Grade 0, 0402; Manufacturer: Vishay-Dale; Power_W: 63mW; TempCo: 100 ppm/C; Value_Code: 1k00; Value: 1.00k; EIA_Code: E96; Res_ohm: 1k; SizeX_mm: 1; SizeY_mm: 0.5; SizeZ_mm: 0.6; Value2: 0.063W; AEC Qualified: Y; VDC_V: 50V; AEC Category: Q200; AEC Grade: 0
R156 = CMP-0026512-2: RES, 6.04 k, 1%, 0.063 W, AEC-Q200 Grade 0, 0402; Manufacturer: Vishay-Dale; Power_W: 63mW; TempCo: 100 ppm/C; Value_Code: 6k04; Value: 6.04k; EIA_Code: E96; SizeX_mm: 1; SizeY_mm: 0.5; SizeZ_mm: 0.6; Value2: 0.063W; AEC Qualified: Y; VDC_V: 50V; AEC Category: Q200; AEC Grade: 0
R172 = CMP-0025960-3: RES, 10.5 k, 1%, 0.063 W, AEC-Q200 Grade 0, 0402; Manufacturer: Vishay-Dale; Power_W: 63mW; TempCo: 100 ppm/C; Value_Code: 10k5; Value: 10.5k; EIA_Code: E96; SizeX_mm: 1; SizeY_mm: 0.5; SizeZ_mm: 0.6; Value2: 0.063W; AEC Qualified: Y; VDC_V: 50V; AEC Category: Q200; AEC Grade: 0
R189 = CMP-0091690-1: RES 0 OHM JUMPER 1/4W 0603; Manufacturer: Stackpole Electronics; Power_W: 250mW; AEC Grade: Grade 0; AEC Qualified: Yes; SizeZ_mm: 0.7mm; Value: 0
R217 R221 R227 R228 R231 R232 R235 R236 = CMP-0027021-3: RES, 10, 5%, 0.05 W, 0201; Manufacturer: Yageo America; Power_W: 50mW; TempCo: 350 ppm/C; Value_Code: 10R0; U/M: EA; Value: 10; EIA_Code: E24; SizeX_mm: 0.6; SizeY_mm: 0.3; SizeZ_mm: 0.26; Value2: 0.05W; SizeArea_mm2: 0.18; AEC Qualified: N; VDC_V: 25V; AEC Category: Q200
R276 R277 = CMP-0026244-2: RES, 2.94 k, 1%, 0.063 W, AEC-Q200 Grade 0, 0402; Manufacturer: Vishay-Dale; Power_W: 63mW; TempCo: 100 ppm/C; Value_Code: 2k94; Value: 2.94k; EIA_Code: E96; SizeX_mm: 1; SizeY_mm: 0.5; SizeZ_mm: 0.6; Value2: 0.063W; AEC Qualified: Y; VDC_V: 50V; AEC Category: Q200; AEC Grade: 0
R278 R279 = CMP-0025950-3: RES, 100 k, 1%, 0.063 W, AEC-Q200 Grade 0, 0402; Manufacturer: Vishay-Dale; Power_W: 63mW; TempCo: 100 ppm/C; Value: 100k; EIA_Code: E96; SizeX_mm: 1; SizeY_mm: 0.5; SizeZ_mm: 0.6; Value2: 0.063W; AEC Qualified: Y; VDC_V: 50V; AEC Category: Q200; AEC Grade: 0
R280 = CMP-0026890-5: RES, 2.2 k, 5%, 0.063 W, AEC-Q200 Grade 0, 0402; Manufacturer: Vishay-Dale; Power_W: 63mW; TempCo: 200 ppm/C; Value_Code: 2k20; Value: 2.2k; EIA_Code: E24; SizeX_mm: 1; SizeY_mm: 0.5; SizeZ_mm: 0.6; Value2: 0.063W; AEC Qualified: Y; VDC_V: 50V; AEC Category: Q200; AEC Grade: 0
R380 R381 R386 = CMP-0026299-2: RES, 33.2, 1%, 0.063 W, AEC-Q200 Grade 0, 0402; Manufacturer: Vishay-Dale; Power_W: 63mW; TempCo: 100 ppm/C; Value_Code: 33R2; Value: 33.2; EIA_Code: E96; SizeX_mm: 1; SizeY_mm: 0.5; SizeZ_mm: 0.6; Value2: 0.063W; AEC Qualified: Y; VDC_V: 50V; AEC Category: Q200; AEC Grade: 0
TP1 TP4 = CMP-0078143-3: TEST POINT.  No entry in BOM.
TP7 TP9 = CMP-0055138-1: Test Point, Miniature, Black, TH; Manufacturer: Keystone; CNHeader: FALSE; Green_Lifecycle: Active; Green_REACh: Passed; ContactFinish: Silver; CT: TRUE
U28 = CMP-0005318-2: 2-Kb, 4-Kb, 8-Kb and 16-Kb I2C CMOS Serial EEPROM, SOIC-8; Manufacturer: ON Semiconductor; SizeAreaWB_mm2: 55.131; SizeZ_mm: 1.75; SizeX_mm: 5.99; SizeY_mm: 4.9; SizeArea_mm2: 29.351
U29 = CMP-0098489-4: Manufacturer: Texas Instruments; SizeZ_mm: 1.234mm; Standoff Height: 0.216mm; AEC Category: Q200; CompType: IC
Y3 = CMP-0001431-1: 50 MHz ±15ppm Crystal 8pF 50 Ohms 4-SMD, No Lead; Manufacturer: NDK; Frequency Stability: 50ppm; Frequency_Fixed: 50MHz; SizeZ_mm: 0.5mm; AEC Qualified: Yes; AEC Grade: Grade 1; Esr: 50
Y7 = CMP-0094615-2: Crystal replacement: Ultra-low Power LVCMOS Oscillator 4-pin, VSON 3.2 x 2.5 x 0.9mm; Manufacturer: Texas Instruments; AEC Qualified: No; Standoff Height: 0mm; Min Supply Voltage: 2.375V; TaMin_C: -40°C; Load Capacitance: 15pF; Frequency Stability: 20ppm; AEC Category: Q200; Frequency_Fixed: 50MHz; CompType: IC; SizeZ_mm: 1mm; Max Supply Voltage: 3.465V; TJmax_C: +135°C; TaMax_C: +105°C; Max Supply Current: 4mA

## Sheet PROC158A_PWR_Reference.SchDoc
size 431 x 279 mm; Date: Not shown in title block; ApprovedBy: Not shown in title block; CheckedBy: Not shown in title block; Author: Not shown in title block; CompanyName: Not shown in title block; Engineer: Not shown in title block; Organization: Not shown in title block; Address1: Not shown in title block; Address2: Not shown in title block; Address3: Not shown in title block; Address4: Not shown in title block; DocumentNumber: 3; Revision: Use project parameter SCH_Rev; SheetNumber: 3; SheetTotal: 24; PageSetup: Record=PageOptions¦CenterHorizontal=True¦CenterVertical=True¦PrintScale=1.00¦XCorrection=1.00¦YCorrection=1.00¦PrintKind=0¦BorderSize=5000000¦LeftOffset=0¦BottomOffset=0¦Orientation=2¦PaperLength=1000¦PaperWidth=1000¦Scale=100¦PaperSource=15¦PrintQuality=600¦MediaType=1¦DitherType=10¦PaperKind=Letter¦PrintScaleMode=1
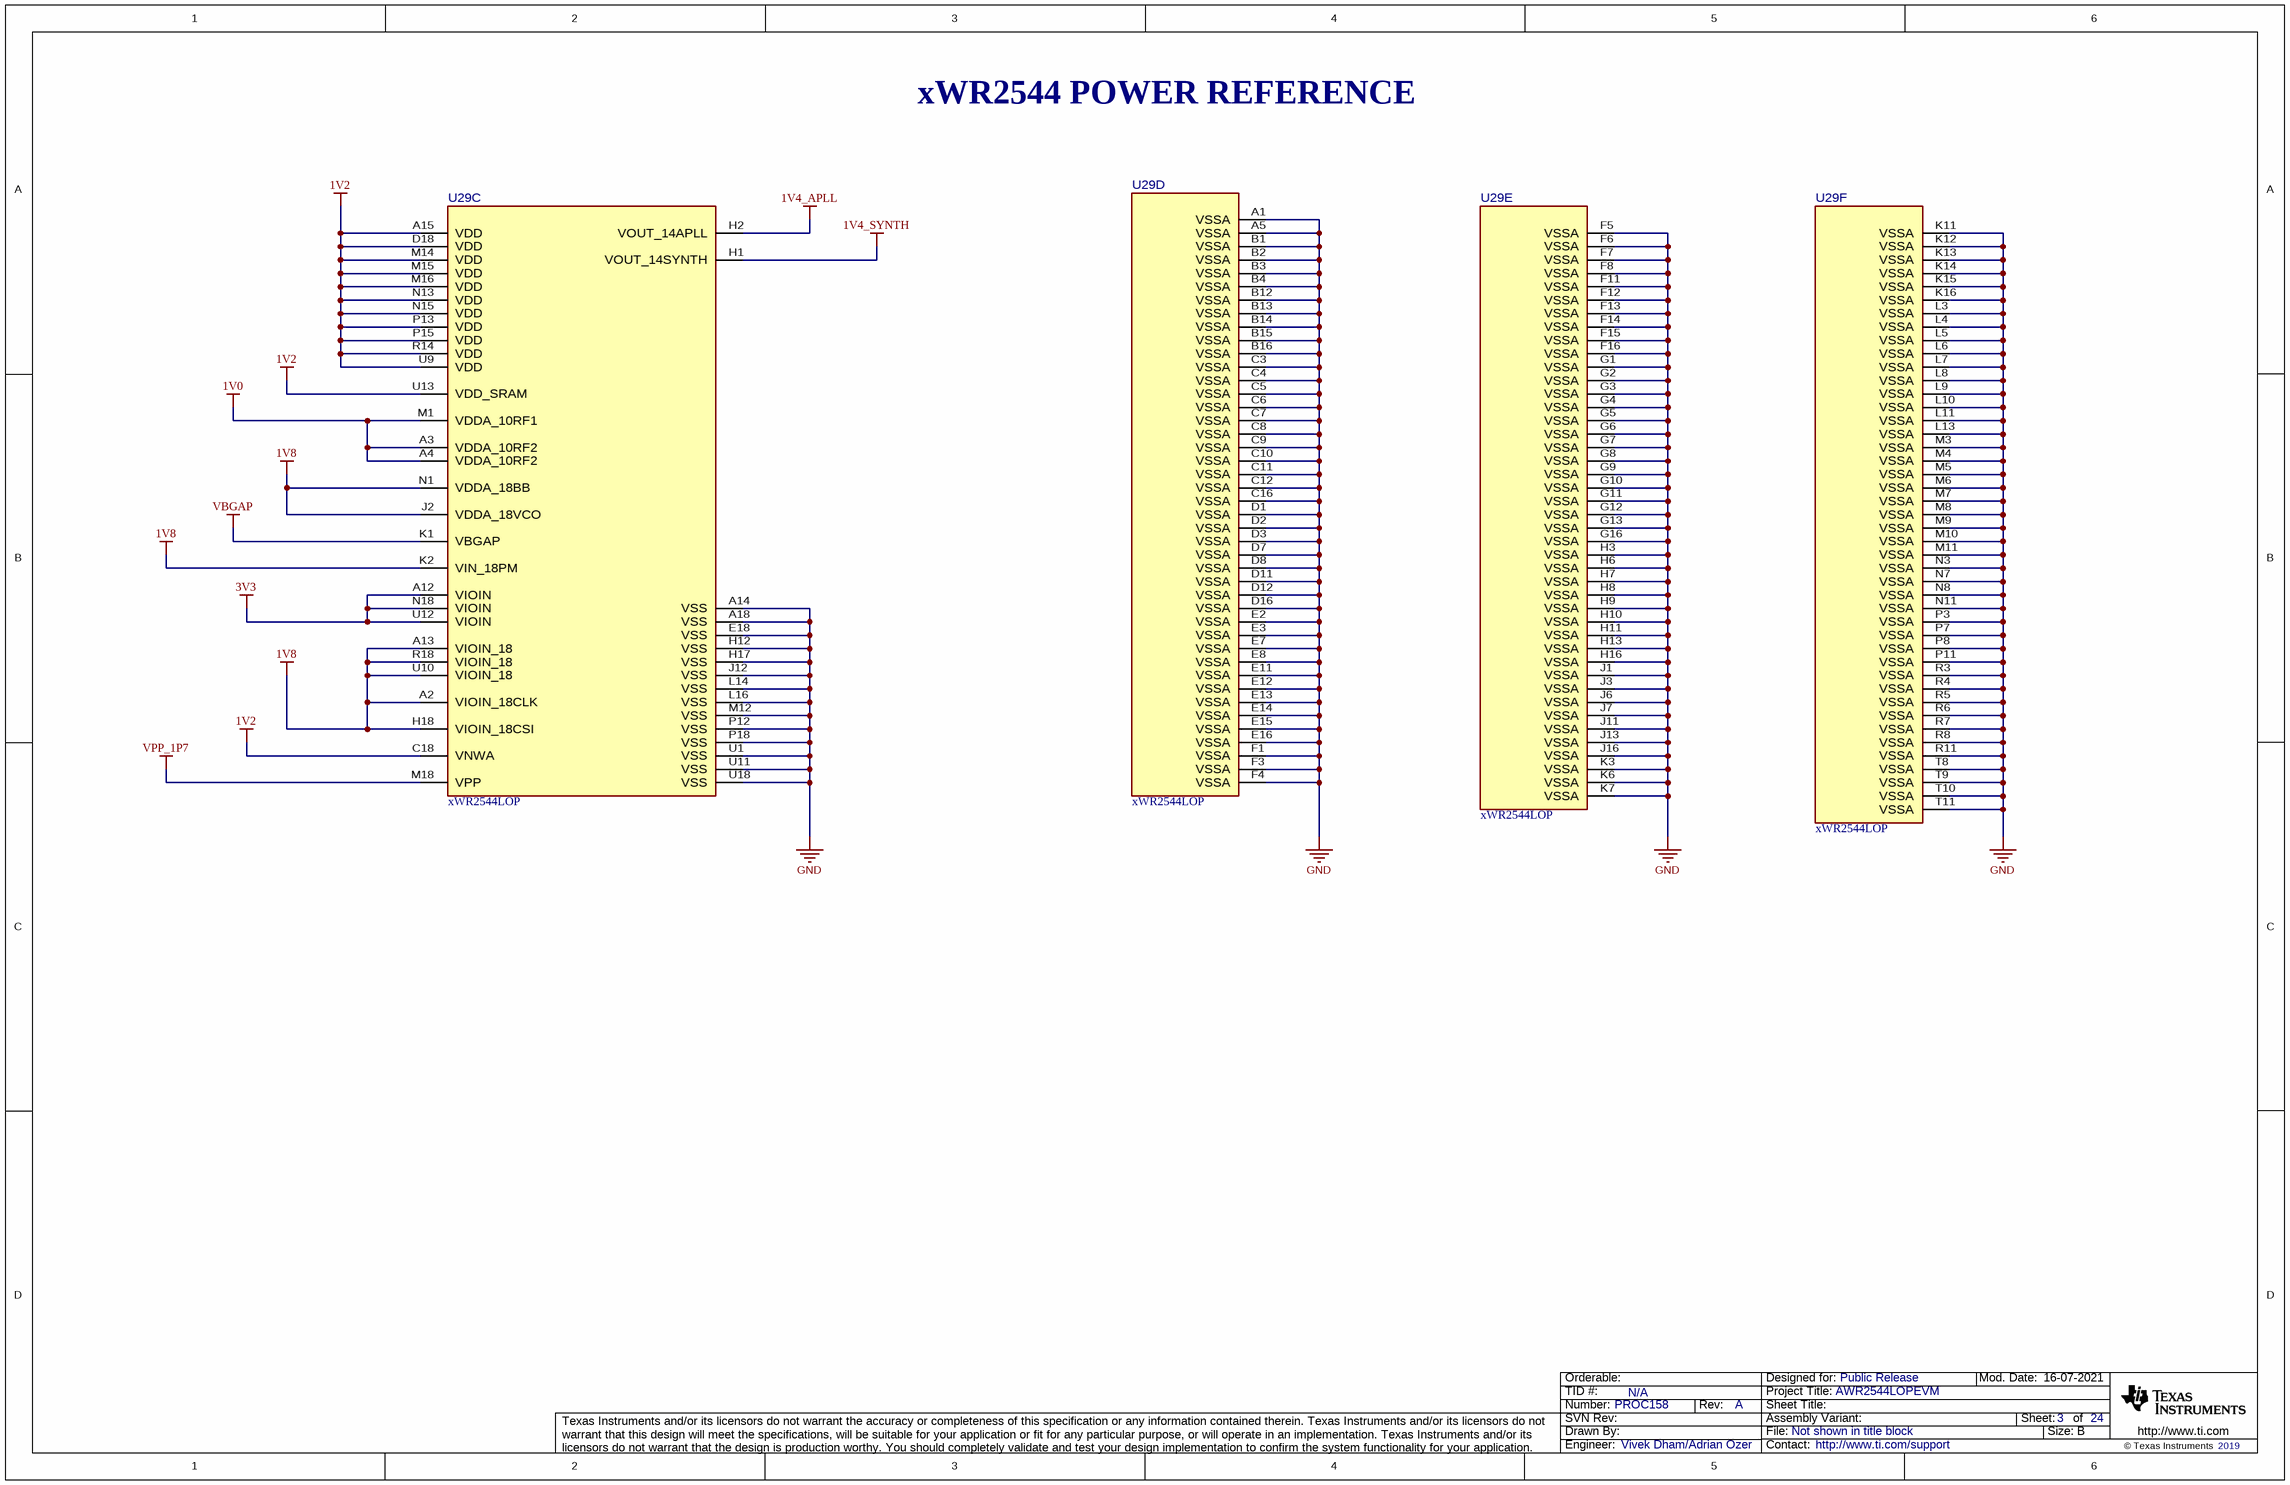
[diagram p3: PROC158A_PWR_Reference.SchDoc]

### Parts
U29  xWR2544LOP  [0-IPC_C]  (parts C,D,E,F of 6)

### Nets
1V0: U29.A3(VDDA_10RF2) U29.A4(VDDA_10RF2) U29.M1(VDDA_10RF1)
1V2: U29.A15(VDD) U29.C18(VNWA) U29.D18(VDD) U29.M14(VDD) U29.M15(VDD) U29.M16(VDD) U29.N13(VDD) U29.N15(VDD) U29.P13(VDD) U29.P15(VDD) U29.R14(VDD) U29.U9(VDD) U29.U13(VDD_SRAM)
1V4_APLL: U29.H2(VOUT_14APLL)
1V4_SYNTH: U29.H1(VOUT_14SYNTH)
1V8: U29.A2(VIOIN_18CLK) U29.A13(VIOIN_18) U29.H18(VIOIN_18CSI) U29.J2(VDDA_18VCO) U29.K2(VIN_18PM) U29.N1(VDDA_18BB) U29.R18(VIOIN_18) U29.U10(VIOIN_18)
3V3: U29.A12(VIOIN) U29.N18(VIOIN) U29.U12(VIOIN)
GND: U29.A1(VSSA) U29.A5(VSSA) U29.A14(VSS) U29.A18(VSS) U29.B1(VSSA) U29.B2(VSSA) U29.B3(VSSA) U29.B4(VSSA) U29.B12(VSSA) U29.B13(VSSA) U29.B14(VSSA) U29.B15(VSSA) U29.B16(VSSA) U29.C3(VSSA) U29.C4(VSSA) U29.C5(VSSA) U29.C6(VSSA) U29.C7(VSSA) U29.C8(VSSA) U29.C9(VSSA) U29.C10(VSSA) U29.C11(VSSA) U29.C12(VSSA) U29.C16(VSSA) U29.D1(VSSA) U29.D2(VSSA) U29.D3(VSSA) U29.D7(VSSA) U29.D8(VSSA) U29.D11(VSSA) U29.D12(VSSA) U29.D16(VSSA) U29.E2(VSSA) U29.E3(VSSA) U29.E7(VSSA) U29.E8(VSSA) U29.E11(VSSA) U29.E12(VSSA) U29.E13(VSSA) U29.E14(VSSA) U29.E15(VSSA) U29.E16(VSSA) U29.E18(VSS) U29.F1(VSSA) U29.F3(VSSA) U29.F4(VSSA) U29.F5(VSSA) U29.F6(VSSA) U29.F7(VSSA) U29.F8(VSSA) U29.F11(VSSA) U29.F12(VSSA) U29.F13(VSSA) U29.F14(VSSA) U29.F15(VSSA) U29.F16(VSSA) U29.G1(VSSA) U29.G2(VSSA) U29.G3(VSSA) U29.G4(VSSA) U29.G5(VSSA) U29.G6(VSSA) U29.G7(VSSA) U29.G8(VSSA) U29.G9(VSSA) U29.G10(VSSA) U29.G11(VSSA) U29.G12(VSSA) U29.G13(VSSA) U29.G16(VSSA) U29.H3(VSSA) U29.H6(VSSA) U29.H7(VSSA) U29.H8(VSSA) U29.H9(VSSA) U29.H10(VSSA) U29.H11(VSSA) U29.H12(VSS) U29.H13(VSSA) U29.H16(VSSA) U29.H17(VSS) U29.J1(VSSA) U29.J3(VSSA) U29.J6(VSSA) U29.J7(VSSA) U29.J11(VSSA) U29.J12(VSS) U29.J13(VSSA) U29.J16(VSSA) U29.K3(VSSA) U29.K6(VSSA) U29.K7(VSSA) U29.K11(VSSA) U29.K12(VSSA) U29.K13(VSSA) U29.K14(VSSA) U29.K15(VSSA) U29.K16(VSSA) U29.L3(VSSA) U29.L4(VSSA) U29.L5(VSSA) U29.L6(VSSA) U29.L7(VSSA) U29.L8(VSSA) U29.L9(VSSA) U29.L10(VSSA) U29.L11(VSSA) U29.L13(VSSA) U29.L14(VSS) U29.L16(VSS) U29.M3(VSSA) U29.M4(VSSA) U29.M5(VSSA) U29.M6(VSSA) U29.M7(VSSA) U29.M8(VSSA) U29.M9(VSSA) U29.M10(VSSA) U29.M11(VSSA) U29.M12(VSS) U29.N3(VSSA) U29.N7(VSSA) U29.N8(VSSA) U29.N11(VSSA) U29.P3(VSSA) U29.P7(VSSA) U29.P8(VSSA) U29.P11(VSSA) U29.P12(VSS) U29.P18(VSS) U29.R3(VSSA) U29.R4(VSSA) U29.R5(VSSA) U29.R6(VSSA) U29.R7(VSSA) U29.R8(VSSA) U29.R11(VSSA) U29.T8(VSSA) U29.T9(VSSA) U29.T10(VSSA) U29.T11(VSSA) U29.U1(VSS) U29.U11(VSS) U29.U18(VSS)
VBGAP: U29.K1(VBGAP)
VPP_1P7: U29.M18(VPP)

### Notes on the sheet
- xWR2544 POWER REFERENCE

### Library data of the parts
U29 = CMP-0098489-4: as U29 on sheet PROC158A_IO_Reference

## Sheet PROC158A_Decoupling_Reference.SchDoc
size 431 x 279 mm; Date: Not shown in title block; ApprovedBy: Not shown in title block; CheckedBy: Not shown in title block; Author: Not shown in title block; CompanyName: Not shown in title block; Engineer: Not shown in title block; Organization: Not shown in title block; Address1: Not shown in title block; Address2: Not shown in title block; Address3: Not shown in title block; Address4: Not shown in title block; DocumentNumber: 4; Revision: Use project parameter SCH_Rev; SheetNumber: 4; SheetTotal: 24; PageSetup: Record=PageOptions¦CenterHorizontal=True¦CenterVertical=True¦PrintScale=1.00¦XCorrection=1.00¦YCorrection=1.00¦PrintKind=0¦BorderSize=5000000¦LeftOffset=0¦BottomOffset=0¦Orientation=2¦PaperLength=1000¦PaperWidth=1000¦Scale=100¦PaperSource=15¦PrintQuality=600¦MediaType=1¦DitherType=10¦PaperKind=Letter¦PrintScaleMode=1
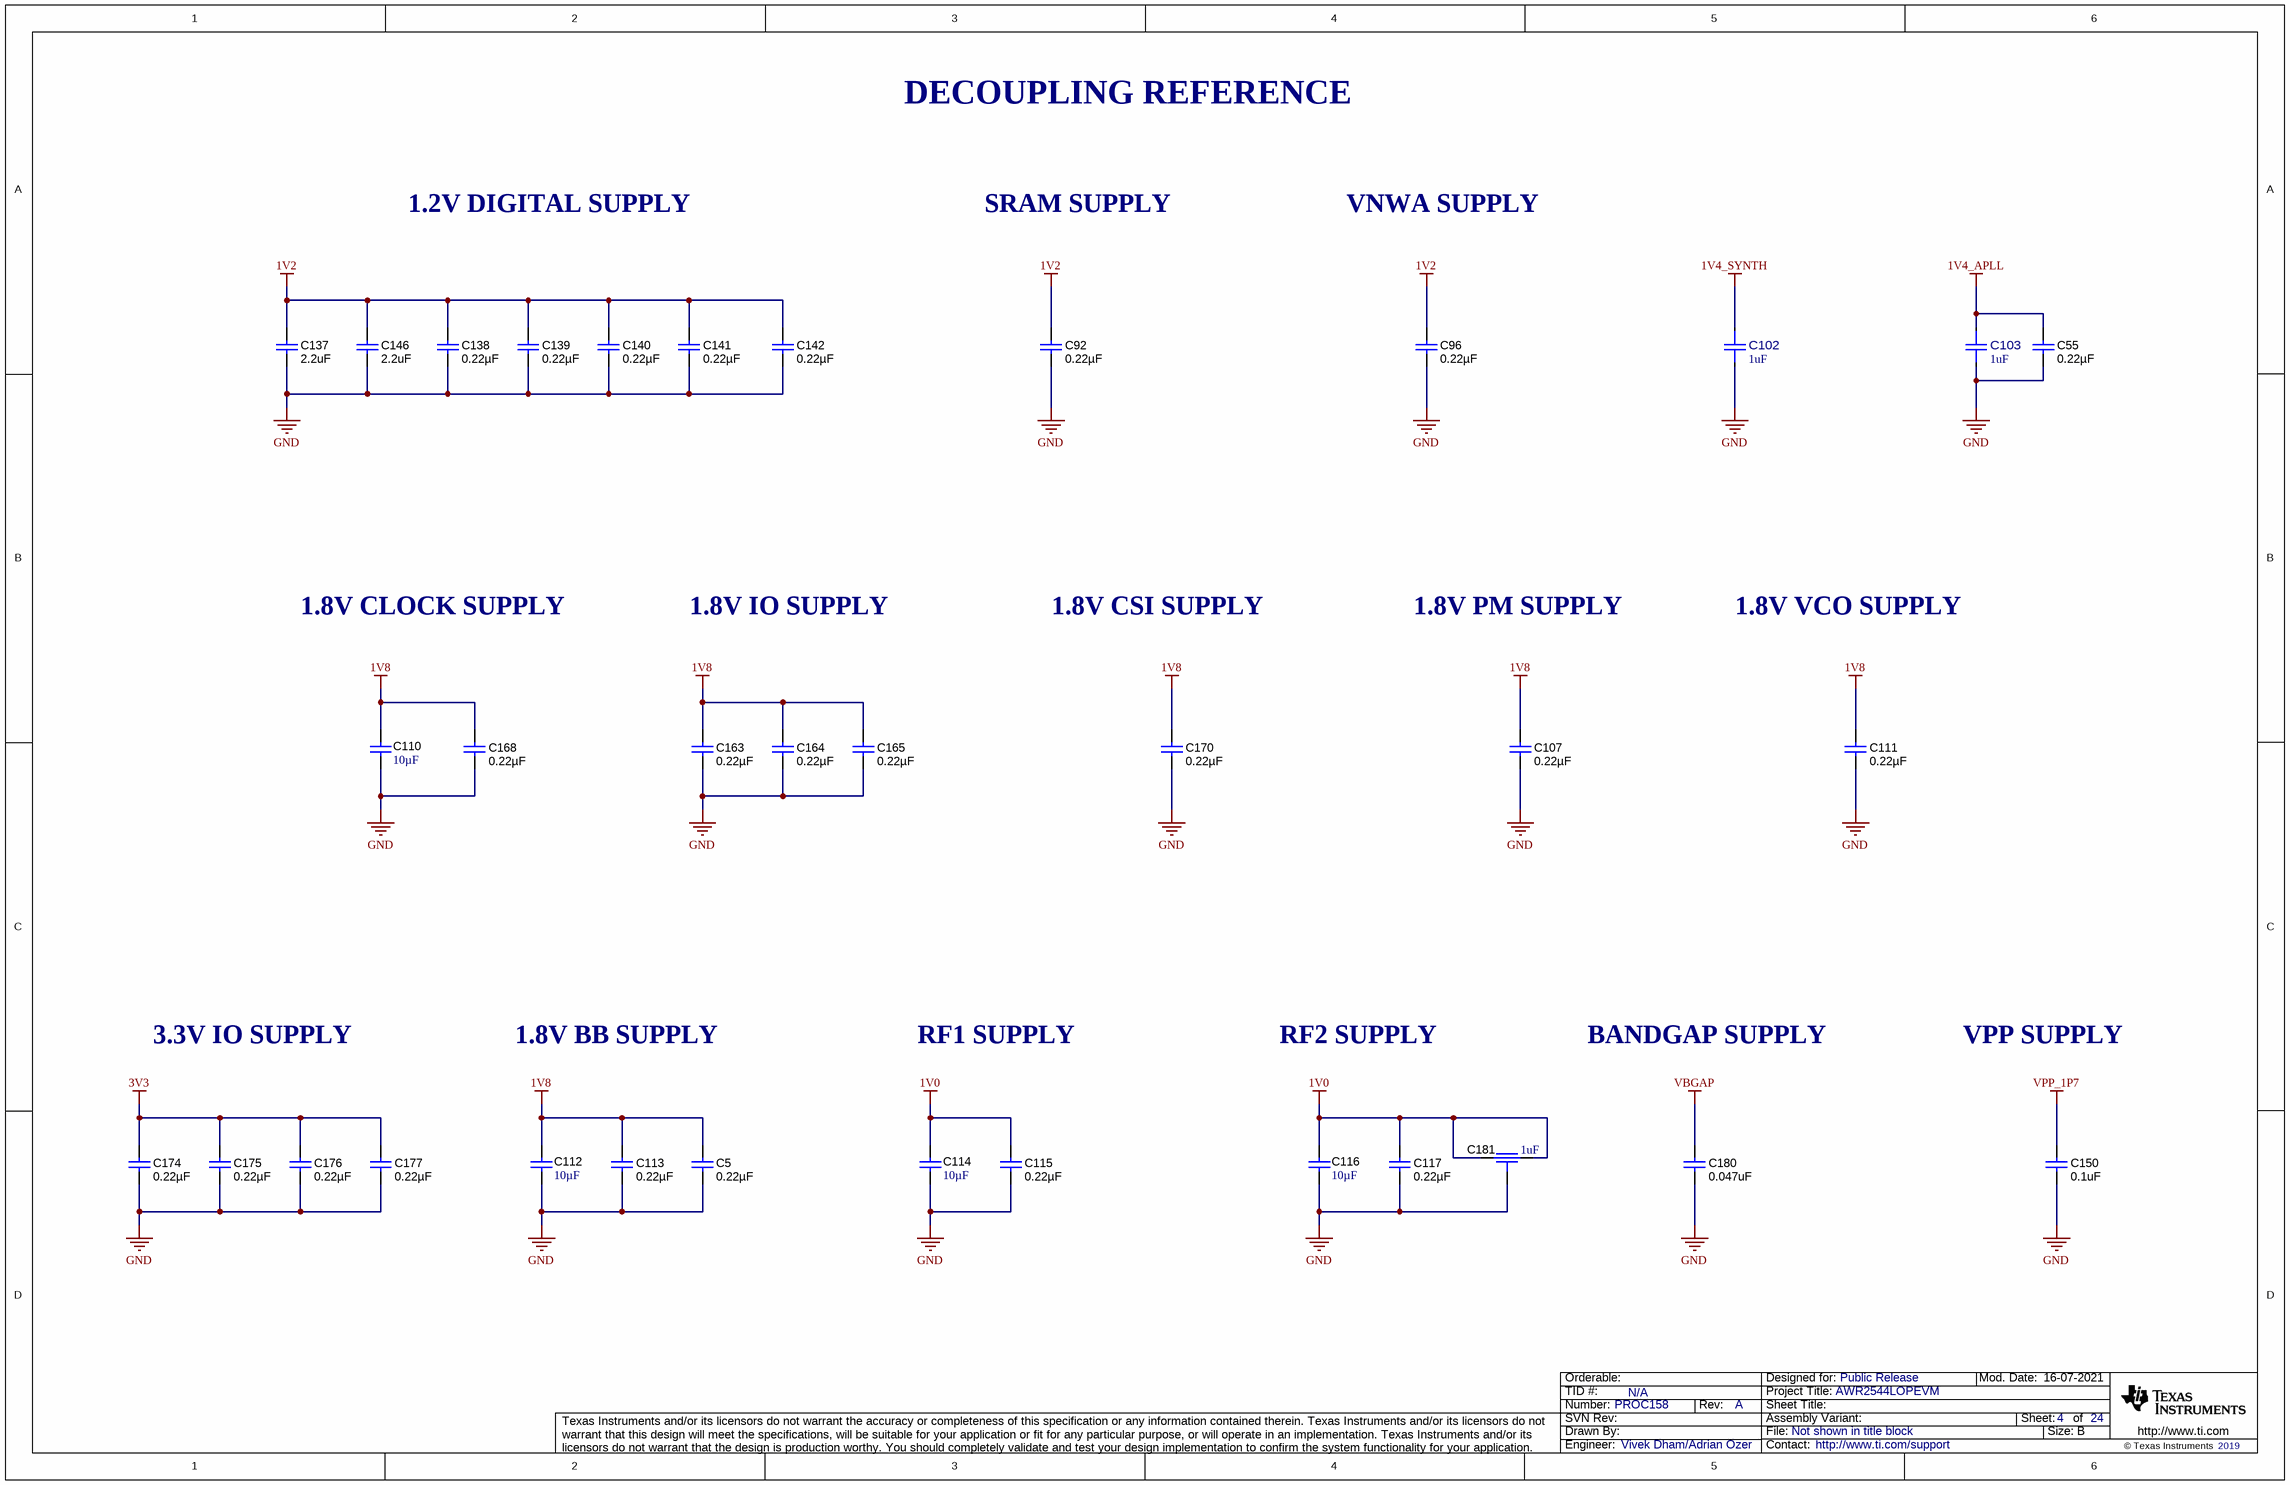
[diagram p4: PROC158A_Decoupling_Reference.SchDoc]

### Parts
C5  ValueDisplayed: 0.22µF  [0402L]  (hidden comment: GCM155R71C224KE02D)
C55  ValueDisplayed: 0.22µF  [0402L]  (hidden comment: GCM155R71C224KE02D)
C92  ValueDisplayed: 0.22µF  [0402L]  (hidden comment: GCM155R71C224KE02D)
C96  ValueDisplayed: 0.22µF  [0402L]  (hidden comment: GCM155R71C224KE02D)
C102  ValueDisplayed: 1uF  [FP-GRT155R70J105KE01D_0402-MFG]  (hidden comment: GRT155R70J105KE01D)
C103  ValueDisplayed: 1uF  [FP-GRT155R70J105KE01D_0402-MFG]  (hidden comment: GRT155R70J105KE01D)
C107  ValueDisplayed: 0.22µF  [0402L]  (hidden comment: GCM155R71C224KE02D)
C110  Cap_F: 10µF  [0805L]  (hidden comment: GCM21BR71A106KE22L)
C111  ValueDisplayed: 0.22µF  [0402L]  (hidden comment: GCM155R71C224KE02D)
C112  Cap_F: 10µF  [0805L]  (hidden comment: GCM21BR71A106KE22L)
C113  ValueDisplayed: 0.22µF  [0402L]  (hidden comment: GCM155R71C224KE02D)
C114  Cap_F: 10µF  [0805L]  (hidden comment: GCM21BR71A106KE22L)
C115  ValueDisplayed: 0.22µF  [0402L]  (hidden comment: GCM155R71C224KE02D)
C116  Cap_F: 10µF  [0805L]  (hidden comment: GCM21BR71A106KE22L)
C117  ValueDisplayed: 0.22µF  [0402L]  (hidden comment: GCM155R71C224KE02D)
C137  ValueDisplayed: 2.2uF  [0603L]  (hidden comment: GCM188R70J225KE22D)
C138  ValueDisplayed: 0.22µF  [0402L]  (hidden comment: GCM155R71C224KE02D)
C139  ValueDisplayed: 0.22µF  [0402L]  (hidden comment: GCM155R71C224KE02D)
C140  ValueDisplayed: 0.22µF  [0402L]  (hidden comment: GCM155R71C224KE02D)
C141  ValueDisplayed: 0.22µF  [0402L]  (hidden comment: GCM155R71C224KE02D)
C142  ValueDisplayed: 0.22µF  [0402L]  (hidden comment: GCM155R71C224KE02D)
C146  ValueDisplayed: 2.2uF  [0603L]  (hidden comment: GCM188R70J225KE22D)
C150  ValueDisplayed: 0.1uF  [0402L]  (hidden comment: GCM155R71C104KA55D)
C163  ValueDisplayed: 0.22µF  [0402L]  (hidden comment: GCM155R71C224KE02D)
C164  ValueDisplayed: 0.22µF  [0402L]  (hidden comment: GCM155R71C224KE02D)
C165  ValueDisplayed: 0.22µF  [0402L]  (hidden comment: GCM155R71C224KE02D)
C168  ValueDisplayed: 0.22µF  [0402L]  (hidden comment: GCM155R71C224KE02D)
C170  ValueDisplayed: 0.22µF  [0402L]  (hidden comment: GCM155R71C224KE02D)
C174  ValueDisplayed: 0.22µF  [0402L]  (hidden comment: GCM155R71C224KE02D)
C175  ValueDisplayed: 0.22µF  [0402L]  (hidden comment: GCM155R71C224KE02D)
C176  ValueDisplayed: 0.22µF  [0402L]  (hidden comment: GCM155R71C224KE02D)
C177  ValueDisplayed: 0.22µF  [0402L]  (hidden comment: GCM155R71C224KE02D)
C180  ValueDisplayed: 0.047uF  [0402L]  (hidden comment: CGA2B3X7R1H473K050BB)
C181  ValueDisplayed: 1uF  [FP-NFM18HC105C1C3D_0603-MFG]  (hidden comment: NFM18HC105C1C3D)

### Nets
1V0: C114.1 C115.2 C116.1 C117.2 C181.1 C181.3
1V2: C92.2 C96.2 C137.2 C138.2 C139.2 C140.2 C141.2 C142.2 C146.2
1V4_APLL: C55.2 C103.1
1V4_SYNTH: C102.1
1V8: C5.2 C107.2 C110.1 C111.2 C112.1 C113.2 C163.2 C164.2 C165.2 C168.2 C170.2
3V3: C174.2 C175.2 C176.2 C177.2
GND: C5.1 C55.1 C92.1 C96.1 C102.2 C103.2 C107.1 C110.2 C111.1 C112.2 C113.1 C114.2 C115.1 C116.2 C117.1 C137.1 C138.1 C139.1 C140.1 C141.1 C142.1 C146.1 C150.1 C163.1 C164.1 C165.1 C168.1 C170.1 C174.1 C175.1 C176.1 C177.1 C180.2 C181.2
VBGAP: C180.1
VPP_1P7: C150.2

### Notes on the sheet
- DECOUPLING REFERENCE
- 1.2V DIGITAL SUPPLY
- SRAM SUPPLY
- VNWA SUPPLY
- 1.8V CLOCK SUPPLY
- 1.8V IO SUPPLY
- 1.8V CSI SUPPLY
- 1.8V PM SUPPLY
- 1.8V VCO SUPPLY
- 3.3V IO SUPPLY
- 1.8V BB SUPPLY
- RF1 SUPPLY
- RF2 SUPPLY
- BANDGAP SUPPLY
- VPP SUPPLY

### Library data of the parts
C5 C55 C92 C96 C107 C111 C113 C115 C117 C138-C142 C163-C165 C168 C170 C174-C177 = CMP-0078265-1: CAP, CERM, 0.22 µF, 16 V,+/- 10%, X7R, AEC-Q200 Grade 1, 0402; Manufacturer: MuRata; TaMin_C: -55°C; Polarized: N; SizeAreaWB_mm2: 3; U/M: EA; Value: 0.22uF; TaMax_C: 125°C; SizeZ_mm: 0.6; SizeX_mm: 1; SizeY_mm: 0.5; Cap_Case: 0402; Value2: 16V; CompType: Capacitor; AEC Qualified: Y; Cap_F: 220nF; AEC Category: Q200
C102 C103 = CMP-0088425-1: 1µF ±10% 6.3V Ceramic Capacitor X7R 0402 (1005 Metric); Manufacturer: Murata; AEC Grade: Grade 1; SizeZ_mm: 0.55mm; AEC Qualified: Yes; TempCo: 15%
C110 C112 C114 C116 = CMP-0008017-2: CAP, CERM, 10 uF, 10 V, +/- 10%, X7R, 0805; Manufacturer: MuRata; TaMin_C: -55°C; Polarized: N; SizeAreaWB_mm2: 6.75; Value1: Unknown; U/M: EA; Value: 10uF; TaMax_C: 125°C; SizeZ_mm: 1.45; SizeX_mm: 2; SizeY_mm: 1.25; Cap_Case: 0805; Value2: 10V; SizeArea_mm2: 2.5; AEC Category: Q200
C137 C146 = CMP-0007134-5: CAP, CERM, 2.2 uF, 6.3 V, +/- 10%, X7R, AEC-Q200 Grade 1, 0603; Manufacturer: MuRata; TaMin_C: -55°C; Polarized: N; SizeAreaWB_mm2: 4.68; Value1: Unknown; U/M: EA; Value: 2.2uF; TaMax_C: 125°C; SizeZ_mm: 1; SizeX_mm: 1.6; SizeY_mm: 0.8; Cap_Case: 0603; Value2: 6.3V; SizeArea_mm2: 1.28; AEC Qualified: Y; Cap_F: 2.2µF; AEC Category: Q200
C150 = CMP-0006351-2: CAP, CERM, 0.1 uF, 16 V, +/- 10%, X7R, 0402; Manufacturer: MuRata; TaMin_C: -55°C; Polarized: N; SizeAreaWB_mm2: 3; Value1: Unknown; U/M: EA; Value: 0.1uF; TaMax_C: 125°C; SizeZ_mm: 0.6; SizeX_mm: 1; SizeY_mm: 0.5; Cap_Case: 0402; Value2: 16V; Cap_F: 100nF; AEC Category: Q200
C180 = CMP-0006330-2: CAP, CERM, 0.047 uF, 50 V, +/- 10%, X7R, AEC-Q200 Grade 1, 0402; Manufacturer: TDK; TaMin_C: -55°C; ESR_ohm: 0.06407; Polarized: N; SizeAreaWB_mm2: 3; Value1: 0.06407 ohm; U/M: EA; TaMax_C: 125°C; SizeZ_mm: 0.6; SizeX_mm: 1; SizeY_mm: 0.5; Cap_Case: 0402; Value2: 50V; AEC Qualified: Y; Cap_F: 47nF; IRMS_A: 646.122mA; AEC Category: Q200
C181 = CMP-0088247-2: 3 Terminals Low ESL Chip Multilayer Ceramic Capacitors for Automotive; Manufacturer: Murata; VDC_V: 16V; SizeZ_mm: 0.7mm; Tolerance_%: 20%; AEC Grade: Grade 1; Cap_F: 1µF; AEC Qualified: Yes

## Sheet PROC158A_QSPI_Flash_Reference.SchDoc
size 431 x 279 mm; Date: Not shown in title block; ApprovedBy: Not shown in title block; CheckedBy: Not shown in title block; Author: Not shown in title block; CompanyName: Not shown in title block; Engineer: Not shown in title block; Organization: Not shown in title block; Address1: Not shown in title block; Address2: Not shown in title block; Address3: Not shown in title block; Address4: Not shown in title block; DocumentNumber: 5; Revision: Use project parameter SCH_Rev; SheetNumber: 5; SheetTotal: 24; PageSetup: Record=PageOptions¦CenterHorizontal=True¦CenterVertical=True¦PrintScale=1.00¦XCorrection=1.00¦YCorrection=1.00¦PrintKind=0¦BorderSize=5000000¦LeftOffset=0¦BottomOffset=0¦Orientation=2¦PaperLength=1000¦PaperWidth=1000¦Scale=100¦PaperSource=15¦PrintQuality=600¦MediaType=1¦DitherType=10¦PaperKind=Letter¦PrintScaleMode=1
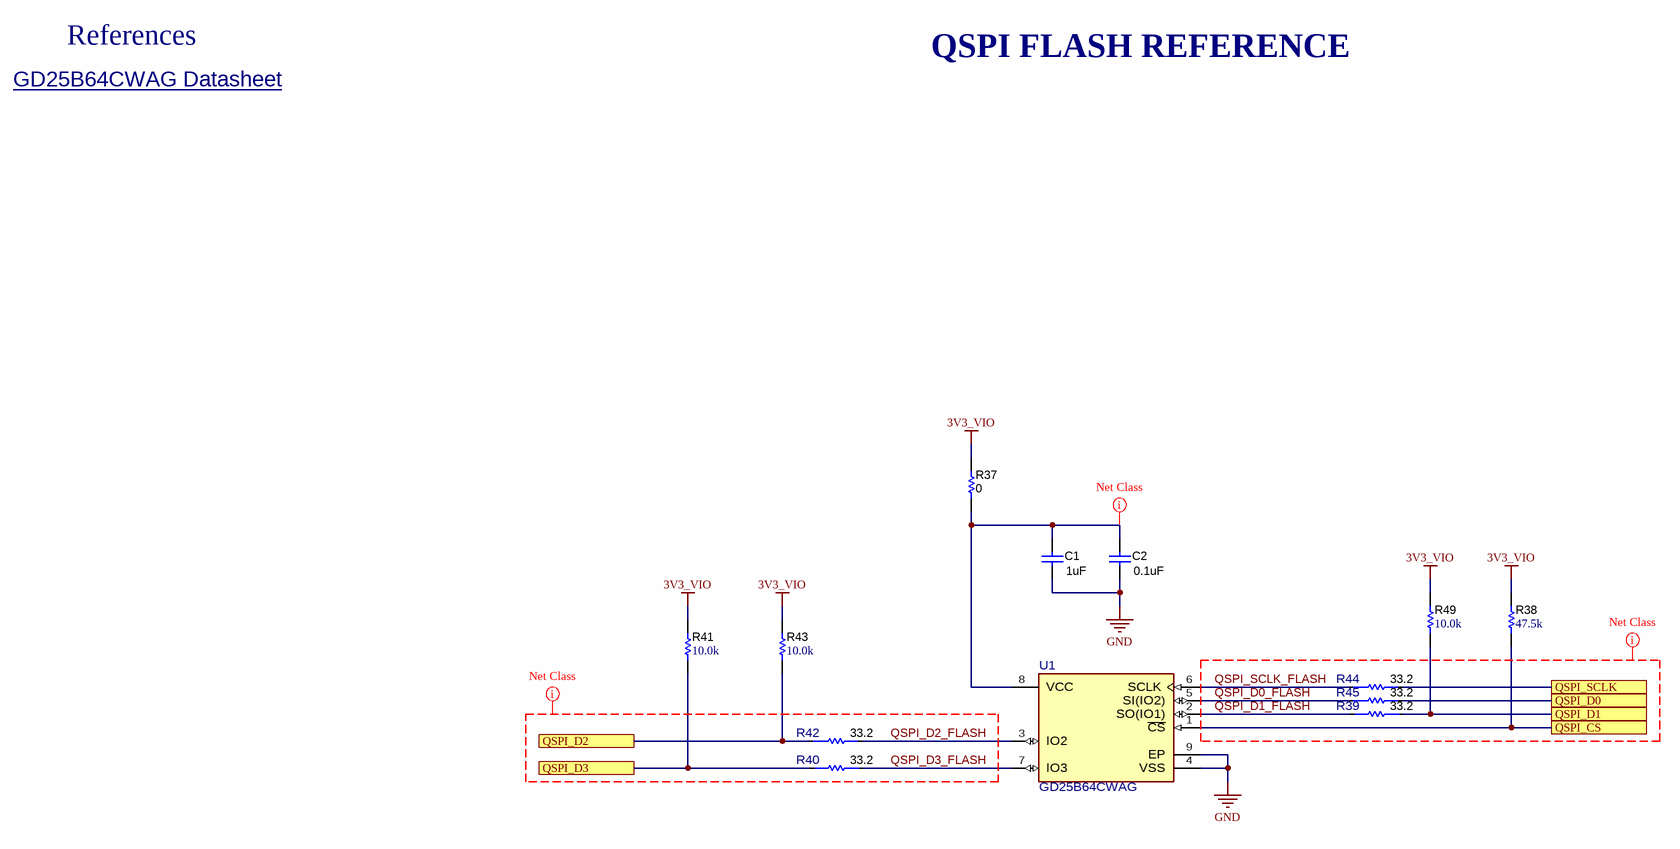
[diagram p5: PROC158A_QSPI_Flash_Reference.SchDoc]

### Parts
C1  ValueDisplayed: 1uF  [0603L]  (hidden comment: GCM188R71C105KA64D)
C2  ValueDisplayed: 0.1uF  [0402L]  (hidden comment: CGA2B3X7R1H104K050BB)
R37  ValueDisplayed: 0  [0402L]  (hidden comment: ERJ-2GE0R00X)
R38  ValueDisplayed: 47.5k  [0402L]  (hidden comment: CRCW040247K5FKED)
R39  Res_ohm: 33.2  [FP-ERJ-1GNF33R2C_0201-MFG]  (hidden comment: ERJ-1GNF33R2C)
R40  Res_ohm: 33.2  [FP-ERJ-1GNF33R2C_0201-MFG]  (hidden comment: ERJ-1GNF33R2C)
R41  ValueDisplayed: 10.0k  [0402L]  (hidden comment: CRCW040210K0FKED)
R42  Res_ohm: 33.2  [FP-ERJ-1GNF33R2C_0201-MFG]  (hidden comment: ERJ-1GNF33R2C)
R43  ValueDisplayed: 10.0k  [0402L]  (hidden comment: CRCW040210K0FKED)
R44  Res_ohm: 33.2  [FP-ERJ-1GNF33R2C_0201-MFG]  (hidden comment: ERJ-1GNF33R2C)
R45  Res_ohm: 33.2  [FP-ERJ-1GNF33R2C_0201-MFG]  (hidden comment: ERJ-1GNF33R2C)
R49  ValueDisplayed: 10.0k  [0402L]  (hidden comment: CRCW040210K0FKED)
U1  GD25B64CWAG  [FP-GD25B64CWAG_WSON8-IPC_C]

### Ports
QSPI_CS, QSPI_D0, QSPI_D1, QSPI_D2, QSPI_D3, QSPI_SCLK

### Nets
3V3_VIO: R37.1 R38.2 R41.2 R43.2 R49.2
GND: C1.1 C2.1 U1.4(VSS) U1.9(EP)
QSPI_CS: R38.1 U1.1(~{CS}) ; port QSPI_CS
QSPI_D0: R45.2 ; port QSPI_D0
QSPI_D0_FLASH: R45.1 U1.5(SI(IO2))
QSPI_D1: R39.1 R49.1 ; port QSPI_D1
QSPI_D1_FLASH: R39.2 U1.2(SO(IO1))
QSPI_D2: R42.1 R43.1 ; port QSPI_D2
QSPI_D2_FLASH: R42.2 U1.3(IO2)
QSPI_D3: R40.2 R41.1 ; port QSPI_D3
QSPI_D3_FLASH: R40.1 U1.7(IO3)
QSPI_SCLK: R44.2 ; port QSPI_SCLK
QSPI_SCLK_FLASH: R44.1 U1.6(SCLK)
NetC1_2: C1.2 C2.2 R37.2 U1.8(VCC)

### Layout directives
net class QSPI: QSPI_D0_FLASH, QSPI_D1_FLASH, QSPI_D2_FLASH, QSPI_D3_FLASH, QSPI_SCLK_FLASH
net class PWR: NetC1_2

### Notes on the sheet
- References
- QSPI FLASH REFERENCE
- GD25B64CWAG Datasheet <https://www.gigadevice.com/datasheet/gd25b64c/>

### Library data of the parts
C1 = CMP-0007136-5: CAP, CERM, 1 uF, 16 V, +/- 10%, X7R, AEC-Q200 Grade 1, 0603; Manufacturer: MuRata; TaMin_C: -55°C; Polarized: N; SizeAreaWB_mm2: 4.68; Value1: Unknown; U/M: EA; Value: 1uF; TaMax_C: 125°C; SizeZ_mm: 1; SizeX_mm: 1.6; SizeY_mm: 0.8; Cap_Case: 0603; Value2: 16V; SizeArea_mm2: 1.28; AEC Qualified: Y; Cap_F: 1µF; AEC Category: Q200
C2 = CMP-0006325-2: CAP, CERM, 0.1 uF, 50 V, +/- 10%, X7R, AEC-Q200 Grade 1, 0402; Manufacturer: TDK; TaMin_C: -55°C; ESR_ohm: 0.039064; Polarized: N; SizeAreaWB_mm2: 3; Value1: 0.039064 ohm; U/M: EA; Value: 0.1uF; TaMax_C: 125°C; SizeZ_mm: 0.6; SizeX_mm: 1; SizeY_mm: 0.5; Cap_Case: 0402; Value2: 50V; AEC Qualified: Y; Cap_F: 100nF; IRMS_A: 8.14669dA; AEC Category: Q200
R37 = CMP-0026992-3: as R3 on sheet PROC158A_IO_Reference
R38 = CMP-0026395-2: RES, 47.5 k, 1%, 0.063 W, AEC-Q200 Grade 0, 0402; Manufacturer: Vishay-Dale; Power_W: 63mW; TempCo: 100 ppm/C; Value_Code: 47k5; Value: 47.5k; EIA_Code: E96; SizeX_mm: 1; SizeY_mm: 0.5; SizeZ_mm: 0.6; Value2: 0.063W; AEC Qualified: Y; VDC_V: 50V; AEC Category: Q200; AEC Grade: 0
R39 R40 R42 R44 R45 = CMP-0089575-2: Res Thick Film 0201 33.2 Ohm 1% 0.05W(1/20W) ±200ppm/C Pad SMD Automotive T/R; Manufacturer: Panasonic; TempCo: 200ppm/°C; VDC_V: 25V; AEC Qualified: Yes; SizeZ_mm: 0.26mm; Power_W: 50mW; AEC Grade: Grade 1; Value: 33.2
R41 R43 R49 = CMP-0025958-3: RES, 10.0 k, 1%, 0.063 W, AEC-Q200 Grade 0, 0402; Manufacturer: Vishay-Dale; Power_W: 63mW; TempCo: 100 ppm/C; Value_Code: 10k0; Value: 10.0k; EIA_Code: E96; Res_ohm: 10k; SizeX_mm: 1; SizeY_mm: 0.5; SizeZ_mm: 0.6; Value2: 0.063W; AEC Qualified: Y; VDC_V: 50V; AEC Category: Q200; AEC Grade: 0
U1 = CMP-0091081-1: 3.3V Uniform Sector Dual and Quad Serial Flash SPI 64Mbit 2.7-3.6V WSON8; Manufacturer: GigaDevice; Interface: SPI,Other; Min Supply Voltage: 2.7V; TaMin_C: -40°C; AEC Grade: Grade 1; Memory Size: 64Mbits; Frequency_Fixed: 120MHz; TaMax_C: +125°C; SizeZ_mm: 0.8mm; Standoff Height: 0mm; AEC Qualified: Yes; Nominal Supply Current: 13-15mA; Max Supply Voltage: 3.6V; Access Time: 7ns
